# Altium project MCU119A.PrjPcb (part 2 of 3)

## Sheet MCU119A_USB_and_Power.SchDoc
size 431 x 279 mm; Date: Not shown in title block; ApprovedBy: Not shown in title block; CheckedBy: Not shown in title block; Author: Not shown in title block; CompanyName: Not shown in title block; Engineer: Not shown in title block; Organization: Not shown in title block; Address1: Not shown in title block; Address2: Not shown in title block; Address3: Not shown in title block; Address4: Not shown in title block; DocumentNumber: 7; Revision: Use project parameter SCH_Rev; SheetNumber: 5; SheetTotal: 8; PageSetup: Record=PageOptions¦CenterHorizontal=True¦CenterVertical=True¦PrintScale=1.00¦XCorrection=1.00¦YCorrection=1.00¦PrintKind=0¦BorderSize=5000000¦LeftOffset=0¦BottomOffset=0¦Orientation=2¦PaperLength=1000¦PaperWidth=1000¦Scale=100¦PaperSource=15¦PrintQuality=600¦MediaType=1¦DitherType=10¦PaperKind=Letter¦PrintScaleMode=1
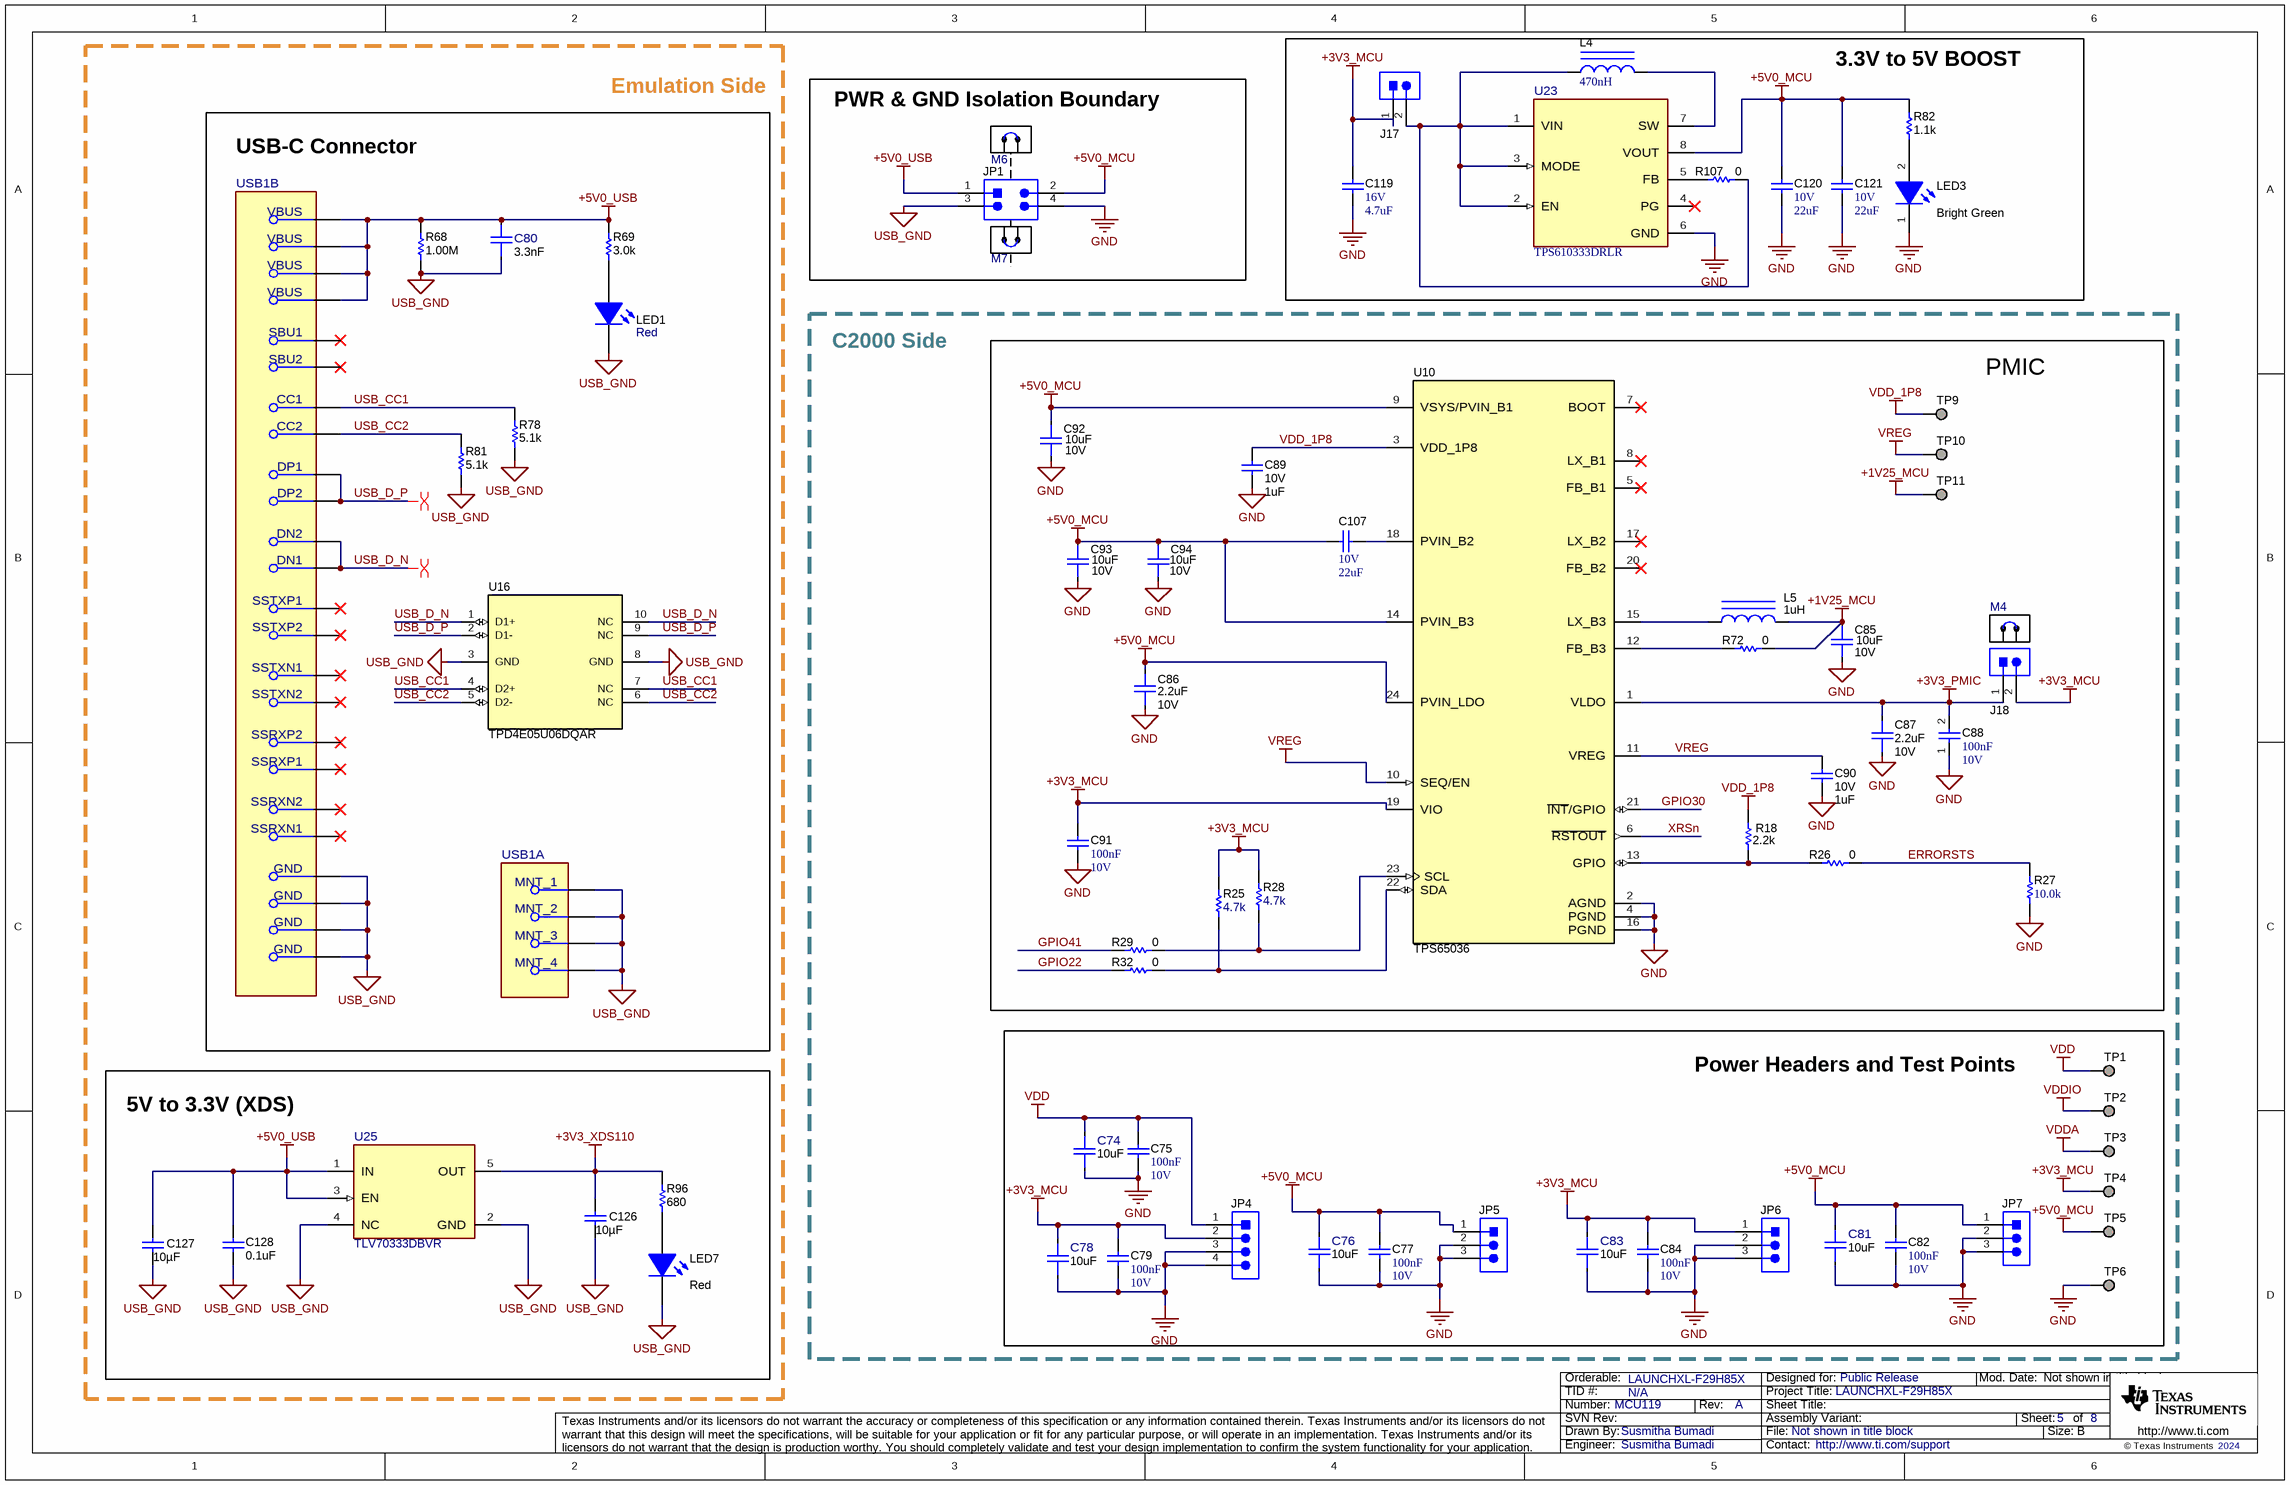
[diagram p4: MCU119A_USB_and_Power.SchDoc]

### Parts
C74  ValueDisplayed: 10uF  [FP-CC0603KRX5R6BB106_0603-MFG]  (hidden comment: CC0603KRX5R6BB106)
C75  Cap_F: 100nF  VDC_V: 10V  [0603]  (hidden comment: C0603C104K8RACTU)
C76  ValueDisplayed: 10uF  [FP-CC0603KRX5R6BB106_0603-MFG]  (hidden comment: CC0603KRX5R6BB106)
C77  Cap_F: 100nF  VDC_V: 10V  [0603]  (hidden comment: C0603C104K8RACTU)
C78  ValueDisplayed: 10uF  [FP-CC0603KRX5R6BB106_0603-MFG]  (hidden comment: CC0603KRX5R6BB106)
C79  Cap_F: 100nF  VDC_V: 10V  [0603]  (hidden comment: C0603C104K8RACTU)
C80  ValueDisplayed: 3.3nF  [FP-885012205064_0402-MFG]  (hidden comment: 885012205064)
C81  ValueDisplayed: 10uF  [FP-CC0603KRX5R6BB106_0603-MFG]  (hidden comment: CC0603KRX5R6BB106)
C82  Cap_F: 100nF  VDC_V: 10V  [0603]  (hidden comment: C0603C104K8RACTU)
C83  ValueDisplayed: 10uF  [FP-CC0603KRX5R6BB106_0603-MFG]  (hidden comment: CC0603KRX5R6BB106)
C84  Cap_F: 100nF  VDC_V: 10V  [0603]  (hidden comment: C0603C104K8RACTU)
C85  VDC_V: 10V  ValueDisplayed: 10uF  [FP-CGA4J3X7S1A106K125AE_0805-MFG]  (hidden comment: CGA4J3X7S1A106K125AE)
C86  ValueDisplayed: 2.2uF  VDC_V: 10V  [FP-CGA3E3X7S1A225K080AB_0603-MFG]  (hidden comment: CGA3E3X7S1A225K080AB)
C87  ValueDisplayed: 2.2uF  VDC_V: 10V  [FP-CGA3E3X7S1A225K080AB_0603-MFG]  (hidden comment: CGA3E3X7S1A225K080AB)
C88  Cap_F: 100nF  VDC_V: 10V  [0603]  (hidden comment: C0603C104K8RACTU)
C89  VDC_V: 10V  ValueDisplayed: 1uF  [0402_070]  (hidden comment: GCM155C71A105KE38D)
C90  VDC_V: 10V  ValueDisplayed: 1uF  [0402_070]  (hidden comment: GCM155C71A105KE38D)
C91  Cap_F: 100nF  VDC_V: 10V  [0603]  (hidden comment: C0603C104K8RACTU)
C92  VDC_V: 10V  ValueDisplayed: 10uF  [FP-CGA4J3X7S1A106K125AE_0805-MFG]  (hidden comment: CGA4J3X7S1A106K125AE)
C93  VDC_V: 10V  ValueDisplayed: 10uF  [FP-CGA4J3X7S1A106K125AE_0805-MFG]  (hidden comment: CGA4J3X7S1A106K125AE)
C94  VDC_V: 10V  ValueDisplayed: 10uF  [FP-CGA4J3X7S1A106K125AE_0805-MFG]  (hidden comment: CGA4J3X7S1A106K125AE)
C107  VDC_V: 10V  ValueDisplayed: 22uF  [0603]  (hidden comment: GRM188R61A226ME15D)
C119  VDC_V: 16V  ValueDisplayed: 4.7uF  [0603]  (hidden comment: GRM188R61C475KAAJ)
C120  VDC_V: 10V  ValueDisplayed: 22uF  [0603]  (hidden comment: GRM188R61A226ME15D)
C121  VDC_V: 10V  ValueDisplayed: 22uF  [0603]  (hidden comment: GRM188R61A226ME15D)
C126  ValueDisplayed: 10µF  [0402_080]  (hidden comment: 0402ZD106MAT2A)
C127  ValueDisplayed: 10µF  [0402_080]  (hidden comment: 0402ZD106MAT2A)
C128  ValueDisplayed: 0.1uF  [0402]  (hidden comment: 885012205037)
J17  61300211121  [WURTH_61300211121]  (value not drawn)
J18  61300211121  [WURTH_61300211121]  (value not drawn)
JP1  TSM-102-01-L-DV  [Samtec_TSM-102-01-x-DV]  (value not drawn)
JP4  61300411121  [WURTH_61300411121]  (value not drawn)
JP5  61300311121  [WURTH_61300311121]  (value not drawn)
JP6  61300311121  [WURTH_61300311121]  (value not drawn)
JP7  61300311121  [WURTH_61300311121]  (value not drawn)
L4  ValueDisplayed: 470nH  [IHHP-1008AB]  (hidden comment: IHHP1008ABERR47M01)
L5  ValueDisplayed: 1uH  [TFM252012]  (hidden comment: TFM252012ALMA1R0MTAA)
LED1  value Red  [WL-SMCW_RED_0805]  (hidden comment: 150080SS75000)
LED3  value Bright Green  [WL-SMCW_Green_0805]  (hidden comment: 150080VS75000)
LED7  value Red  [WL-SMCW_RED_0805]  (hidden comment: 150080SS75000)
M4  60900213421  [Wurth_60900213421]  (value not drawn)
M6  60900213421  [Wurth_60900213421]  (value not drawn)
M7  60900213421  [Wurth_60900213421]  (value not drawn)
R18  ValueDisplayed: 2.2k  [0402]  (hidden comment: CRCW04022K20JNED)
R25  ValueDisplayed: 4.7k  [0402]  (hidden comment: CRCW04024K70JNED)
R26  ValueDisplayed: 0  [0402]  (hidden comment: RC0402JR-070RL)
R27  ValueDisplayed: 10.0k  [0402]  (hidden comment: AC0402FR-0710KL)
R28  ValueDisplayed: 4.7k  [0402]  (hidden comment: CRCW04024K70JNED)
R29  ValueDisplayed: 0  [0402]  (hidden comment: RC0402JR-070RL)
R32  ValueDisplayed: 0  [0402]  (hidden comment: RC0402JR-070RL)
R68  ValueDisplayed: 1.00M  [0402]  (hidden comment: CRCW04021M00FKED)
R69  ValueDisplayed: 3.0k  [0603]  (hidden comment: RC0603JR-073KL)
R72  ValueDisplayed: 0  [0402]  (hidden comment: RC0402JR-070RL)
R78  ValueDisplayed: 5.1k  [0603]  (hidden comment: RC0603JR-075K1L)
R81  ValueDisplayed: 5.1k  [0603]  (hidden comment: RC0603JR-075K1L)
R82  ValueDisplayed: 1.1k  [0402]  (hidden comment: CRCW04021K10JNED)
R96  ValueDisplayed: 680  [0402]  (hidden comment: CRCW0402680RJNED)
R107  ValueDisplayed: 0  [0402]  (hidden comment: RC0402JR-070RL)
TP1  TESTPOINT  [TP_50MIL-25MILHOLE]  (value not drawn)  (no BOM)
TP2  TESTPOINT  [TP_50MIL-25MILHOLE]  (value not drawn)  (no BOM)
TP3  TESTPOINT  [TP_50MIL-25MILHOLE]  (value not drawn)  (no BOM)
TP4  TESTPOINT  [TP_50MIL-25MILHOLE]  (value not drawn)  (no BOM)
TP5  TESTPOINT  [TP_50MIL-25MILHOLE]  (value not drawn)  (no BOM)
TP6  TESTPOINT  [TP_50MIL-25MILHOLE]  (value not drawn)  (no BOM)
TP9  TESTPOINT  [TP_50MIL-25MILHOLE]  (value not drawn)  (no BOM)
TP10  TESTPOINT  [TP_50MIL-25MILHOLE]  (value not drawn)  (no BOM)
TP11  TESTPOINT  [TP_50MIL-25MILHOLE]  (value not drawn)  (no BOM)
U10  TPS65036  [RAY0024B-MFG]
U16  TPD4E05U06DQAR  [DQA0010A]
U23  TPS610333DRLR  [DRL0008A-MFG]
U25  TLV70333DBVR  [DBV0005A-MFG]
USB1  MUP-U22001  [FP-MUP-U22001_CONN_USB_8MM94_8MM0-MFG]  (value not drawn)  (parts A,B of 2)

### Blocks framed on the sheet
3.3V to 5V BOOST: C119-C121 J17 L4 LED3 R82 R107 U23
USB-C Connector: C80 LED1 R68 R69 R78 R81 U16 USB1
PWR & GND Isolation Boundary: JP1 M6 M7
PMIC: C85-C94 C107 J18 L5 M4 R18 R25-R29 R32 R72 TP9-TP11 U10
5V to 3.3V (XDS): C126-C128 LED7 R96 U25
Power Headers and Test Points: C74-C79 C81-C84 JP4-JP7 TP1-TP6

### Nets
+1V25_MCU: C85.1 L5.2 R72.2 TP11.1
+3V3_MCU: C78.2 C79.1 C83.2 C84.1 C91.1 C119.1 J17.1 J18.2 JP4.2 JP6.1 R25.2 R28.2 TP4.1 U10.19(VIO)
+3V3_PMIC: C87.2 C88.2 J18.1 U10.1(VLDO)
+3V3_XDS110: C126.1 R96.1 U25.5(OUT)
+5V0_MCU: C76.2 C77.1 C81.2 C82.1 C86.2 C92.1 C93.1 C94.1 C107.2 C120.1 C121.1 JP1.2 JP5.1 JP7.1 R82.2 TP5.1 U10.9(VSYS/PVIN_B1) U10.14(PVIN_B3) U10.24(PVIN_LDO) U23.8(VOUT)
+5V0_USB: C80.2 C127.1 C128.1 JP1.1 R68.2 R69.2 U25.1(IN) U25.3(EN) USB1.A4(VBUS) USB1.A9(VBUS) USB1.B4(VBUS) USB1.B9(VBUS)
GND: C74.1 C75.1 C76.1 C77.2 C78.1 C79.2 C81.1 C82.2 C83.1 C84.2 C85.2 C86.1 C87.1 C88.1 C89.2 C90.2 C91.2 C92.2 C93.2 C94.2 C119.2 C120.2 C121.2 JP1.4 JP4.3 JP4.4 JP5.2 JP5.3 JP6.2 JP6.3 JP7.2 JP7.3 LED3.1(K) R27.1 TP6.1 U10.2(AGND) U10.4(PGND) U10.16(PGND) U23.6(GND)
USB_GND: C80.1 C126.2 C127.2 C128.2 JP1.3 LED1.1(K) LED7.1(K) R68.1 R78.1 R81.1 U16.3(GND) U16.8(GND) U25.2(GND) U25.4(NC) USB1.1(MNT_1) USB1.2(MNT_2) USB1.3(MNT_3) USB1.4(MNT_4) USB1.A1(GND) USB1.A12(GND) USB1.B1(GND) USB1.B12(GND)
VDD: C74.2 C75.2 JP4.1 TP1.1
VDD_1P8: C89.1 R18.2 TP9.1 U10.3(VDD_1P8)
VDDA: TP3.1
VDDIO: TP2.1
VREG: C90.1 TP10.1 U10.10(SEQ/EN) U10.11(VREG)
ERRORSTS: R26.2 R27.2
GPIO22: R32.1
GPIO30: U10.21(~{INT}/GPIO)
GPIO41: R29.1
USB_CC1: R78.2 U16.4(D2+) U16.7(NC) USB1.A5(CC1)
USB_CC2: R81.2 U16.5(D2-) U16.6(NC) USB1.B5(CC2)
USB_D_N: U16.1(D1+) U16.10(NC) USB1.A7(DN1) USB1.B7(DN2)
USB_D_P: U16.2(D1-) U16.9(NC) USB1.A6(DP1) USB1.B6(DP2)
XRSn: U10.6(~{RSTOUT})
NetC107_1: C107.1 U10.18(PVIN_B2)
NetJ17_2: J17.2 L4.1 R107.2 U23.1(VIN) U23.2(EN) U23.3(MODE)
NetL4_2: L4.2 U23.7(SW)
NetL5_1: L5.1 U10.15(LX_B3)
NetLED1_2: LED1.2(A) R69.1
NetLED3_2: LED3.2(A) R82.1
NetLED7_2: LED7.2(A) R96.2
NetR18_1: R18.1 R26.1 U10.13(GPIO)
NetR25_1: R25.1 R32.2 U10.22(SDA)
NetR28_1: R28.1 R29.2 U10.23(SCL)
NetR72_1: R72.1 U10.12(FB_B3)
NetR107_1: R107.1 U23.5(FB)

Not connected (* = marked no-connect by the designer): U10 5(FB_B1)* 7(BOOT)* 8(LX_B1)* 17(LX_B2)* 20(FB_B2)*; U23 4(PG)*; USB1 A2(SSTXP1)* A3(SSTXN1)* A8(SBU1)* A10(SSRXN2)* A11(SSRXP2)* B2(SSTXP2)* B3(SSTXN2)* B8(SBU2)* B10(SSRXN1)* B11(SSRXP1)*

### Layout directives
differential pair: USB_D_N, USB_D_P

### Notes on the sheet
- Emulation Side
- C2000 Side

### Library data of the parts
C74 C76 C78 C81 C83 = CMP-0092309-1: Cap Ceramic 10uF 10V X5R 10% SMD 0603 85C Paper T/R; Manufacturer: YAGEO; Cap_F: 10µF; TempCo: 15%; Category 7542B8484461Ae85: Passive Components; Category 4C11811B7D3097D6: Single Components; SizeZ_mm: 1mm; Category F8883582C9A8234F: Capacitors; AEC Qualified: No; Value: 10µF; Category 85Ce48C4B2B95E09: Uncategorized
C75 C77 C79 C82 C84 C88 C91 = CMP-0006862-5: CAP, CERM, 0.1 uF, 10 V, +/- 10%, X7R, 0603; Manufacturer: Kemet; TaMin_C: -55°C; Polarized: N; SizeAreaWB_mm2: 4.68; Value1: Unknown; U/M: EA; Value: 0.1uF; TaMax_C: 125°C; SizeZ_mm: 1; SizeX_mm: 1.6; SizeY_mm: 0.8; SizeArea_mm2: 1.28; AEC Category: Q200
C80 = CMP-0092424-1: Cap Cer 3300pF 50V X7R 0402; Manufacturer: Wurth Electronics; TempCo: 15%; AEC Qualified: No; Value: 3.3nF; SizeZ_mm: 0.55mm; Tolerance_%: 10%
C85 C92-C94 = CMP-0089543-1: 10µF ±10% 10V Ceramic Capacitor X7S 0805 (2012 Metric); Manufacturer: TDK; SizeZ_mm: 1.5mm; AEC Grade: Grade 1; AEC Qualified: Yes; TempCo: 22%
C86 C87 = CMP-0094207-1: Cap Ceramic 2.2uF 10V X7S 10% Pad SMD 0603 +125°C Automotive T/R; Manufacturer: TDK; Tolerance_%: 0.1%; AEC Grade: Grade 1; TempCo: 0.22; Cap_F: 2.2µF; SizeZ_mm: 1.1mm; AEC Qualified: Yes; Value: 2.2µF
C89 C90 = CMP-0006349-2: CAP, CERM, 1 uF, 10 V, +/- 10%, X7S, AEC-Q200 Grade 1, 0402; Manufacturer: MuRata; TaMin_C: -55°C; Polarized: N; SizeAreaWB_mm2: 3; Value1: Unknown; U/M: EA; Value: 1uF; TaMax_C: 125°C; SizeZ_mm: 0.7; SizeX_mm: 1; SizeY_mm: 0.5; Cap_Case: 0402; AEC Qualified: Y; Cap_F: 1µF; AEC Category: Q200
C107 C120 C121 = CMP-0007324-5: CAP, CERM, 22 uF, 10 V, +/- 20%, X5R, 0603; Manufacturer: MuRata; TaMin_C: -55°C; Polarized: N; SizeAreaWB_mm2: 4.68; Value1: Unknown; U/M: EA; Value: 22uF; TaMax_C: 85°C; SizeZ_mm: 1; SizeX_mm: 1.6; SizeY_mm: 0.8; SizeArea_mm2: 1.28; Cap_F: 22µF; AEC Category: Q200
C119 = CMP-0007341-5: CAP, CERM, 4.7 uF, 16 V, +/- 10%, X5R, 0603; Manufacturer: MuRata; TaMin_C: -55°C; Polarized: N; SizeAreaWB_mm2: 4.68; Value1: Unknown; U/M: EA; Value: 4.7uF; TaMax_C: 85°C; SizeZ_mm: 1; SizeX_mm: 1.6; SizeY_mm: 0.8; SizeArea_mm2: 1.28; Cap_F: 4.7µF; AEC Category: Q200
C126 C127 = CMP-0078623-1: CAP, CERM, 10 µF, 10 V,+/- 20%, X5R, 0402; Manufacturer: AVX; SizeAreaWB_mm2: 3; SizeArea_mm2: 0.5; AEC Qualified: N; AEC Category: Q200; Value: 10uF; TaMax_C: 85°C; SizeZ_mm: 0.8; TaMin_C: -55°C; VDC_V: 10V; U/M: EA; SizeX_mm: 1
C128 = CMP-0006228-2: CAP, CERM, 0.1 uF, 16 V, +/- 10%, X7R, 0402; Manufacturer: Wurth Elektronik; TaMin_C: -55°C; Polarized: N; SizeAreaWB_mm2: 3; Value1: Unknown; U/M: EA; Value: 0.1uF; TaMax_C: 125°C; SizeZ_mm: 0.6; SizeX_mm: 1; SizeY_mm: 0.5; Value2: 16V; Cap_F: 100nF; AEC Category: Q200
J17 J18 = CMP-0054794-2: Header, 2.54 mm, 2x1, Gold, TH; Manufacturer: Wurth Elektronik; Shrouded: N; Gender: Male; Green_REACh: Passed; Pitch_mm: 2.54; Green_Lifecycle: Active; Row_Count: 1; Cert_UL: Y
JP1 = CMP-0055559-1: Header, 2.54mm, 2x2, Gold, SMT; Manufacturer: Samtec; CNHeader: TRUE; Shrouded: N; Gender: Male; Cert_CSA: Y; Voltage_V: 475V; Row_Count: 2; Pitch_mm: 2.54; CT: FALSE
JP4 = CMP-0054798-2: Header, 2.54 mm, 4x1, Gold, TH; Manufacturer: Wurth Elektronik; Pitch_mm: 2.54; Gender: Male; Row_Count: 1; Cert_UL: Y; Shrouded: N
JP5-JP7 = CMP-0054796-4: Header, 2.54 mm, 3x1, Gold, TH; Manufacturer: Wurth Elektronik; Green_Lifecycle: Active; Green_REACh: Passed; CNHeader: TRUE; CT: FALSE
L4 = CMP-0063237-1: Inductor, Shielded, 470 nH, 4 A, 0.026 ohm, SMD; Manufacturer: Vishay-Dale; Isat: 4.55A @ 30% inductance drop; Irms: 4A @ 40C rise; SizeAreaWB_mm2: 10.5; DCR_ohm: 26m; Value: 470nH; Imax_A: 4A; SizeZ_mm: 1.2; SizeX_mm: 2.5; SizeY_mm: 2; SizeArea_mm2: 5; AEC Qualified: N; AEC Category: Q200
L5 = CMP-0062879-1: Inductor, Film, 1 uH, 3.7 A, 0.042 ohm, AEC-Q200 Grade 0, SMD; Manufacturer: TDK; Isat: 4.1A @ 30% inductance drop; Irms: 3.7A @ 40C rise; Green_Lifecycle: Not Set; SizeAreaWB_mm2: 10.5; DCR_ohm: 42m; Green_REACh: Incomplete; Value: 1uH; Imax_A: 3.7A; SizeZ_mm: 1.2; SizeX_mm: 2.5; SizeY_mm: 2; SizeArea_mm2: 5; Ind_H: 1µH; AEC Qualified: Y; AEC Grade: 0; AEC Category: Q200
LED1 LED7 = CMP-0002951-3: LED, Red, SMD; Manufacturer: Wurth Elektronik; Type: AlInGaP; Vf_V: 1.9V; Io_A: 30mA; Vr_V: 5V; Ir_A: 25µA; Tjmax_C: 85°C; Power_TotalModule: 72mW; Value1: 0.072W; Angle: 140
LED3 = CMP-0002960-2: LED, Bright Green, SMD; Manufacturer: Wurth Elektronik; Type: AlInGaP; Vf_V: 2V; Io_A: 20mA; Vr_V: 5V; Tjmax_C: 85°C; Power_TotalModule: 72mW; Value1: 0.072W; Angle: 140; U/M: EA
M4 M6 M7 = CMP-0003761-2: Shunt, 2.54mm, Gold, Black; Manufacturer: Wurth Elektronik
R18 = CMP-0026890-5: RES, 2.2 k, 5%, 0.063 W, AEC-Q200 Grade 0, 0402; Manufacturer: Vishay-Dale; Value: 2.2k; Value_Code: 2k20; Power_W: 63mW; Value2: 0.063W; VDC_V: 50V; TempCo: 200 ppm/C; SizeArea_mm2: 0.5; SizeX_mm: 1; SizeZ_mm: 0.6; EIA_Code: E24; AEC Category: Q200; AEC Qualified: Y; AEC Grade: 0
R25 R28 = CMP-0026938-1: RES, 4.7 k, 5%, 0.063 W, 0402; Manufacturer: Vishay-Dale; Power_W: 63mW; TempCo: 200 ppm/C; Value_Code: 4k70; U/M: EA; Value: 4.7k; EIA_Code: E24; SizeX_mm: 1; SizeY_mm: 0.5; SizeZ_mm: 0.6; Value2: 0.063W; VDC_V: 50V; AEC Category: Q200
R26 R29 R32 R72 R107 = CMP-0027004-2: RES, 0, 5%, 0.063 W, 0402; Manufacturer: Yageo America; Power_W: 63mW; TempCo: 200 ppm/C; Value_Code: 0000; U/M: EA; Value: 0; EIA_Code: E24; SizeX_mm: 1; SizeY_mm: 0.5; SizeZ_mm: 0.6; Value2: 0.063W; VDC_V: 50V; AEC Category: Q200
R27 = CMP-0077731-1: RES, 10.0 k, 1%, 0.063 W, AEC-Q200 Grade 0, 0402; Manufacturer: Yageo America; Power_W: 63mW; TempCo: 100 ppm/C; Value_Code: 10k0; U/M: EA; Value: 10.0k; EIA_Code: E96; Res_ohm: 10k; SizeX_mm: 1.0; SizeY_mm: 0.5; SizeZ_mm: 0.6; Value2: 0.063W; AEC Qualified: Y; VDC_V: 50V; AEC Grade: 0; AEC Category: Q200
R68 = CMP-0026100-2: RES, 1.00 M, 1%, 0.063 W, AEC-Q200 Grade 0, 0402; Manufacturer: Vishay-Dale; Value: 1.00Meg; Res_ohm: 1M; Value_Code: 1M00; Power_W: 63mW; Value2: 0.063W; VDC_V: 50V; TempCo: 100 ppm/C; SizeArea_mm2: 0.5; SizeX_mm: 1; SizeZ_mm: 0.6; EIA_Code: E96; AEC Category: Q200; AEC Qualified: Y; AEC Grade: 0
R69 = CMP-0025921-5: RES, 3.0 k, 5%, 0.1 W, 0603; Manufacturer: Yageo; Power_W: 100mW; TempCo: 100 ppm/C; Value_Code: 3k00; Value: 3.0k; EIA_Code: E24; Res_ohm: 3k; SizeX_mm: 1.6; SizeY_mm: 0.8; SizeZ_mm: 1; Value2: 0.1W; SizeArea_mm2: 1.28; AEC Qualified: N; VDC_V: 75V; AEC Category: Q200; SizeAreaWB_mm2: 4.68
R78 R81 = CMP-0025932-5: RES, 5.1 k, 5%, 0.1 W, 0603; Manufacturer: Yageo; Power_W: 100mW; TempCo: 100 ppm/C; Value_Code: 5k10; Value: 5.1k; EIA_Code: E24; SizeX_mm: 1.6; SizeY_mm: 0.8; SizeZ_mm: 1; Value2: 0.1W; SizeArea_mm2: 1.28; AEC Qualified: N; VDC_V: 75V; AEC Category: Q200; SizeAreaWB_mm2: 4.68
R82 = CMP-0026853-5: RES, 1.1 k, 5%, 0.063 W, AEC-Q200 Grade 0, 0402; Manufacturer: Vishay-Dale; Power_W: 63mW; TempCo: 200 ppm/C; Value_Code: 1k10; Value: 1.1k; EIA_Code: E24; SizeX_mm: 1; SizeY_mm: 0.5; SizeZ_mm: 0.6; Value2: 0.063W; AEC Qualified: Y; VDC_V: 50V; AEC Category: Q200; AEC Grade: 0
R96 = CMP-0026962-3: RES, 680, 5%, 0.063 W, AEC-Q200 Grade 0, 0402; Manufacturer: Vishay-Dale; Value: 680; Value_Code: 680R; Power_W: 63mW; Value2: 0.063W; VDC_V: 50V; TempCo: 200 ppm/C; EIA_Code: E24; AEC Category: Q200; AEC Qualified: Y; AEC Grade: 0; SizeArea_mm2: 0.5; SizeX_mm: 1; SizeZ_mm: 0.6
TP1-TP6 TP9-TP11 = CMP-0078143-4: TEST POINT.  No entry in BOM.
U10 = CMP-0119993-1: Automotive Camera PMIC; Manufacturer: Texas Instruments; SizeZ_mm: 1mm; AEC Qualified: Yes; AEC Grade: Grade 1; Max Supply Voltage: 35V; Min Supply Voltage: 4V; Number Of Outputs: 4; Output Voltage: 3-5.5/0.6-3.4/0.6-3.4/1.8-3.4V; Standoff Height: 0mm; TaMax_C: +125°C; TaMin_C: -40°C; TJmax_C: +150°C
U16 = CMP-0073613-3: 4-Channel Ultra-Low-Capacitance IEC ESD Protection Diode, DQA0010A (USON-10); Alternate Manufacturer: Texas Instruments; Green_Lifecycle: Active; SizeAreaWB_mm2: 7.0; Green_REACh: Passed; SizeZ_mm: 0.55; SizeX_mm: 1.0; SizeY_mm: 2.5; CompType: IC; AEC Category: Q200; AEC Qualified: N
U23 = CMP-0122273-1: 5-V, 1.85-A boost converter with power good, output discharge and PFM/PWM control 8-SOT-5X3 -40 to 125; Manufacturer: Texas Instruments; SizeZ_mm: 0.6mm; AEC Qualified: No; Max Supply Voltage: 5.5V; Min Supply Voltage: 1.8V; Nominal Supply Current: 20uA; Number Of Outputs: 1; Output Type: Fixed; Output Voltage: 5V; Standoff Height: 0mm; Switching Frequency: 2.4MHz; TJmax_C: +125°C
U25 = CMP-0091939-1: Linear Voltage Regulator IC Positive Fixed 1 Output 300mA SOT-23-5; Manufacturer: Texas Instruments; SizeZ_mm: 1.45mm; Nominal Supply Current: 35-370uA; TJmax_C: +125°C; Output Voltage: 3.3V; Dropout Voltage: 260mV; Standoff Height: 0mm; Accuracy Percentage: 2%; AEC Qualified: No; Max Supply Voltage: 5.5V; Number Of Outputs: 1; Min Supply Voltage: 2V
USB1 = CMP-0092137-1: Connector, USB Type-C 24 pin Mid Mount dual row Receptacle Surface Mount; Manufacturer: MUP; ContactFinish: Gold,Nickel; Usb Standard: OTHER; AEC Qualified: No; Conn Orientation: Horizontal; Shrouded: true; SizeZ_mm: 2.81mm; Is Female: yes; DUT-Pitch_mm: 0.5mm

## Sheet MCU119A_XDS110_MCU.SchDoc
size 431 x 279 mm; Date: Not shown in title block; ApprovedBy: Not shown in title block; CheckedBy: Not shown in title block; Author: Not shown in title block; CompanyName: Not shown in title block; Engineer: Not shown in title block; Organization: Not shown in title block; Address1: Not shown in title block; Address2: Not shown in title block; Address3: Not shown in title block; Address4: Not shown in title block; DocumentNumber: 8; Revision: Use project parameter SCH_Rev; SheetNumber: 6; SheetTotal: 8; PageSetup: Record=PageOptions¦CenterHorizontal=True¦CenterVertical=True¦PrintScale=1.00¦XCorrection=1.00¦YCorrection=1.00¦PrintKind=0¦BorderSize=5000000¦LeftOffset=0¦BottomOffset=0¦Orientation=2¦PaperLength=1000¦PaperWidth=1000¦Scale=100¦PaperSource=15¦PrintQuality=600¦MediaType=1¦DitherType=10¦PaperKind=Letter¦PrintScaleMode=1
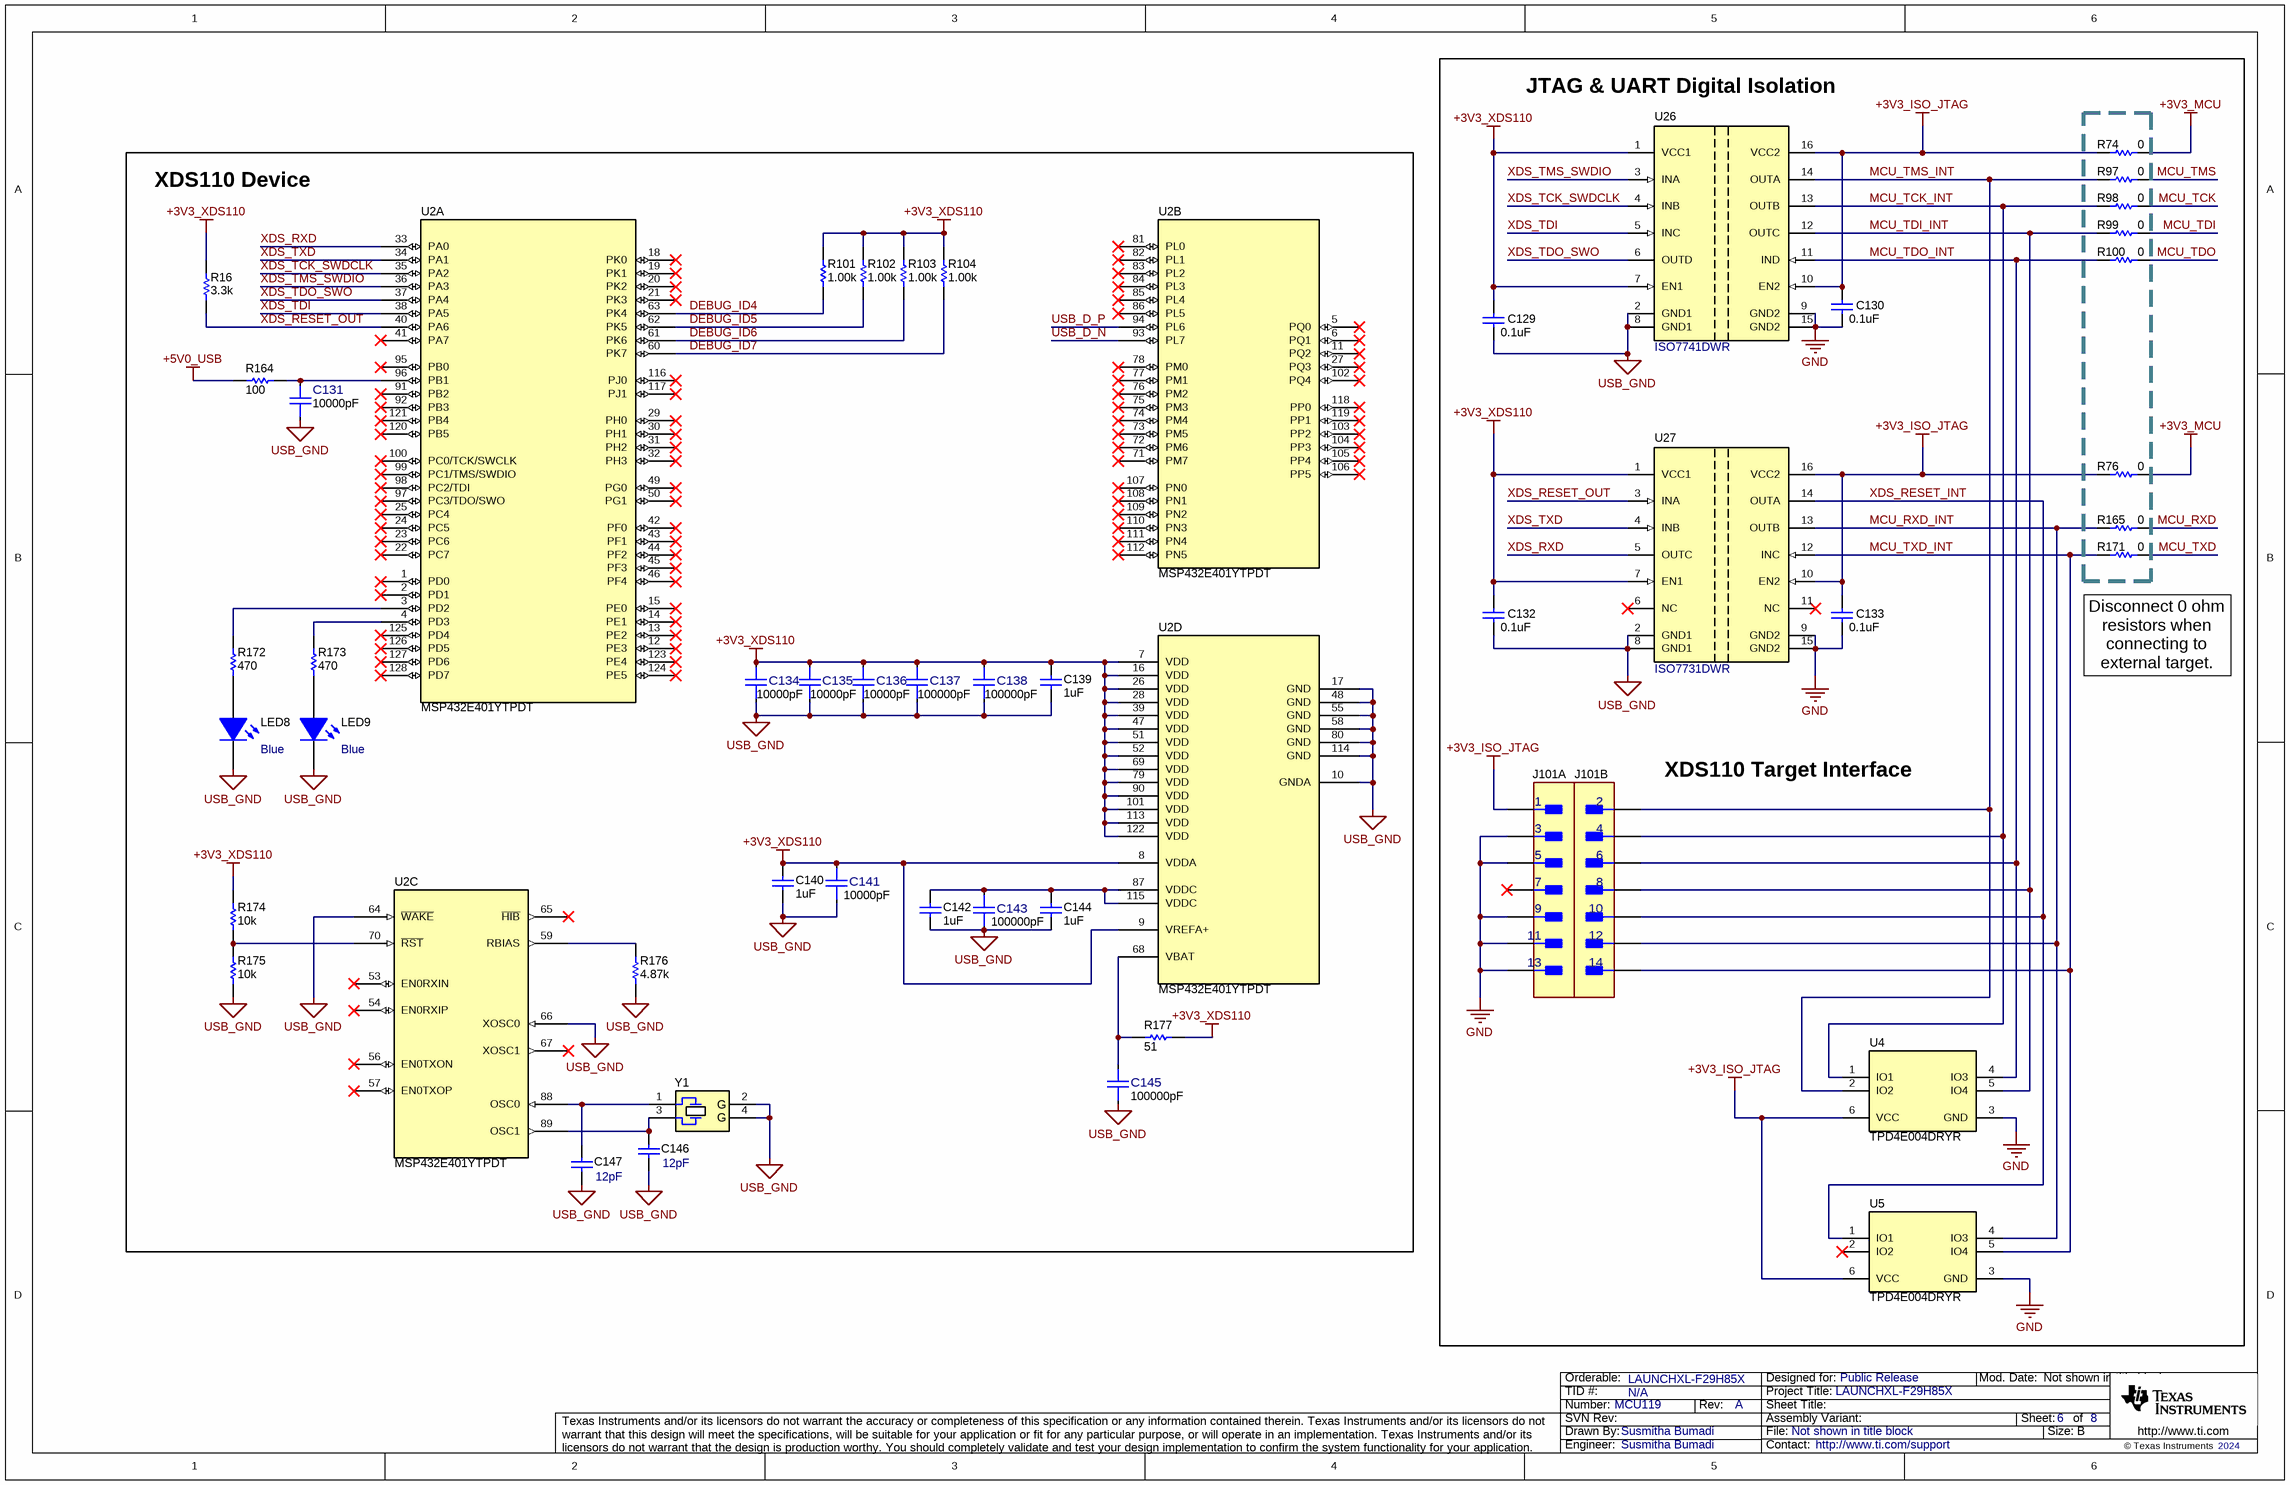
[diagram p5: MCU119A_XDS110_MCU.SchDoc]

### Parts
C129  ValueDisplayed: 0.1uF  [0402]  (hidden comment: 885012205037)
C130  ValueDisplayed: 0.1uF  [0402]  (hidden comment: 885012205037)
C131  ValueDisplayed: 10000pF  [FP-885012205050_0402-MFG]  (hidden comment: 885012205050)
C132  ValueDisplayed: 0.1uF  [0402]  (hidden comment: 885012205037)
C133  ValueDisplayed: 0.1uF  [0402]  (hidden comment: 885012205037)
C134  ValueDisplayed: 10000pF  [FP-885012205050_0402-MFG]  (hidden comment: 885012205050)
C135  ValueDisplayed: 10000pF  [FP-885012205050_0402-MFG]  (hidden comment: 885012205050)
C136  ValueDisplayed: 10000pF  [FP-885012205050_0402-MFG]  (hidden comment: 885012205050)
C137  ValueDisplayed: 100000pF  [FP-885012205018_0402-MFG]  (hidden comment: 885012205018)
C138  ValueDisplayed: 100000pF  [FP-885012205018_0402-MFG]  (hidden comment: 885012205018)
C139  ValueDisplayed: 1uF  [0402]  (hidden comment: 885012105012)
C140  ValueDisplayed: 1uF  [0402]  (hidden comment: 885012105012)
C141  ValueDisplayed: 10000pF  [FP-885012205050_0402-MFG]  (hidden comment: 885012205050)
C142  ValueDisplayed: 1uF  [0402]  (hidden comment: 885012105012)
C143  ValueDisplayed: 100000pF  [FP-885012205018_0402-MFG]  (hidden comment: 885012205018)
C144  ValueDisplayed: 1uF  [0402]  (hidden comment: 885012105012)
C145  ValueDisplayed: 100000pF  [FP-885012205018_0402-MFG]  (hidden comment: 885012205018)
C146  ValueDisplayed: 12pF  [0402]  (hidden comment: CL05C120JB5NNNC)
C147  ValueDisplayed: 12pF  [0402]  (hidden comment: CL05C120JB5NNNC)
J101  FTSH-107-01-F-DV-K  [FP-FTSH-107-01-F-DV-K_HDR14-MFG]  (value not drawn)  (parts A,B of 2)
LED8  value Blue  [LTST-C170TBKT_Blue]  (hidden comment: LTST-C170TBKT)
LED9  value Blue  [LTST-C170TBKT_Blue]  (hidden comment: LTST-C170TBKT)
R16  ValueDisplayed: 3.3k  [0402]  (hidden comment: CRCW04023K30JNED)
R74  ValueDisplayed: 0  [0603]  (hidden comment: ERJ-3GEY0R00V)
R76  ValueDisplayed: 0  [0603]  (hidden comment: ERJ-3GEY0R00V)
R97  ValueDisplayed: 0  [0603]  (hidden comment: ERJ-3GEY0R00V)
R98  ValueDisplayed: 0  [0603]  (hidden comment: ERJ-3GEY0R00V)
R99  ValueDisplayed: 0  [0603]  (hidden comment: ERJ-3GEY0R00V)
R100  ValueDisplayed: 0  [0603]  (hidden comment: ERJ-3GEY0R00V)
R101  ValueDisplayed: 1.00k  [0402]  (hidden comment: CRCW04021K00FKED)
R102  ValueDisplayed: 1.00k  [0402]  (hidden comment: CRCW04021K00FKED)
R103  ValueDisplayed: 1.00k  [0402]  (hidden comment: CRCW04021K00FKED)
R104  ValueDisplayed: 1.00k  [0402]  (hidden comment: CRCW04021K00FKED)
R164  ValueDisplayed: 100  [0402]  (hidden comment: CRCW0402100RJNED)
R165  ValueDisplayed: 0  [0603]  (hidden comment: ERJ-3GEY0R00V)
R171  ValueDisplayed: 0  [0603]  (hidden comment: ERJ-3GEY0R00V)
R172  ValueDisplayed: 470  [0402]  (hidden comment: RC0402FR-07470RL)
R173  ValueDisplayed: 470  [0402]  (hidden comment: RC0402FR-07470RL)
R174  ValueDisplayed: 10k  [0402]  (hidden comment: CRCW040210K0JNED)
R175  ValueDisplayed: 10k  [0402]  (hidden comment: CRCW040210K0JNED)
R176  ValueDisplayed: 4.87k  [0402]  (hidden comment: CRCW04024K87FKED)
R177  ValueDisplayed: 51  [0402]  (hidden comment: CRCW040251R0JNED)
U2  MSP432E401YTPDT  [PDT0128A]  (parts A,B,C,D of 4)
U4  TPD4E004DRYR  [DRY0006A]
U5  TPD4E004DRYR  [DRY0006A]
U26  ISO7741DWR  [DW0016B_HV]
U27  ISO7731DWR  [DW0016B_HV]
Y1  NX3225GA-16.000M-STD-CRG-1  [NDK_NX3225GA]  (value not drawn)

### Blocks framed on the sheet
XDS110 Device: C131 C134-C147 LED8 LED9 R16 R101-R104 R164 R172-R177 U2 Y1

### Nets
+3V3_ISO_JTAG: C130.1 C133.1 J101.1 R74.1 R76.1 U4.6(VCC) U5.6(VCC) U26.10(EN2) U26.16(VCC2) U27.10(EN2) U27.16(VCC2)
+3V3_MCU: R74.2 R76.2
+3V3_XDS110: C129.1 C132.1 C134.2 C135.2 C136.2 C137.2 C138.2 C139.1 C140.1 C141.2 R16.2 R101.2 R102.2 R103.2 R104.2 R174.2 R177.2 U2.7(VDD) U2.8(VDDA) U2.9(VREFA+) U2.16(VDD) U2.26(VDD) U2.28(VDD) U2.39(VDD) U2.47(VDD) U2.51(VDD) U2.52(VDD) U2.69(VDD) U2.79(VDD) U2.90(VDD) U2.101(VDD) U2.113(VDD) U2.122(VDD) U26.1(VCC1) U26.7(EN1) U27.1(VCC1) U27.7(EN1)
+5V0_USB: R164.1
GND: C130.2 C133.2 J101.3 J101.5 J101.9 J101.11 J101.13 U4.3(GND) U5.3(GND) U26.9(GND2) U26.15(GND2) U27.9(GND2) U27.15(GND2)
USB_GND: C129.2 C131.1 C132.2 C134.1 C135.1 C136.1 C137.1 C138.1 C139.2 C140.2 C141.1 C142.2 C143.1 C144.2 C145.1 C146.2 C147.2 LED8.2(K) LED9.2(K) R175.1 R176.1 U2.10(GNDA) U2.17(GND) U2.48(GND) U2.55(GND) U2.58(GND) U2.64(~{WAKE}) U2.66(XOSC0) U2.80(GND) U2.114(GND) U26.2(GND1) U26.8(GND1) U27.2(GND1) U27.8(GND1) Y1.2(GND) Y1.4(GND)
DEBUG_ID4: R101.1 U2.63(PK4)
DEBUG_ID5: R102.1 U2.62(PK5)
DEBUG_ID6: R103.1 U2.61(PK6)
DEBUG_ID7: R104.1 U2.60(PK7)
MCU_RXD: R165.1
MCU_RXD_INT: J101.12 R165.2 U5.4(IO3) U27.13(OUTB)
MCU_TCK: R98.1
MCU_TCK_INT: J101.4 R98.2 U4.1(IO1) U26.13(OUTB)
MCU_TDI: R99.1
MCU_TDI_INT: J101.8 R99.2 U4.5(IO4) U26.12(OUTC)
MCU_TDO: R100.1
MCU_TDO_INT: J101.6 R100.2 U4.4(IO3) U26.11(IND)
MCU_TMS: R97.1
MCU_TMS_INT: J101.2 R97.2 U4.2(IO2) U26.14(OUTA)
MCU_TXD: R171.1
MCU_TXD_INT: J101.14 R171.2 U5.5(IO4) U27.12(INC)
USB_D_N: U2.93(PL7)
USB_D_P: U2.94(PL6)
XDS_RESET_INT: J101.10 U5.1(IO1) U27.14(OUTA)
XDS_RESET_OUT: R16.1 U2.40(PA6) U27.3(INA)
XDS_RXD: U2.33(PA0) U27.5(OUTC)
XDS_TCK_SWDCLK: U2.35(PA2) U26.4(INB)
XDS_TDI: U2.38(PA5) U26.5(INC)
XDS_TDO_SWO: U2.37(PA4) U26.6(OUTD)
XDS_TMS_SWDIO: U2.36(PA3) U26.3(INA)
XDS_TXD: U2.34(PA1) U27.4(INB)
NetC131_2: C131.2 R164.2 U2.96(PB1)
NetC142_1: C142.1 C143.2 C144.1 U2.87(VDDC) U2.115(VDDC)
NetC145_2: C145.2 R177.1 U2.68(VBAT)
NetC146_1: C146.1 U2.89(OSC1) Y1.3
NetC147_1: C147.1 U2.88(OSC0) Y1.1
NetLED8_1: LED8.1(A) R172.1
NetLED9_1: LED9.1(A) R173.1
NetR172_2: R172.2 U2.3(PD2)
NetR173_2: R173.2 U2.4(PD3)
NetR174_1: R174.1 R175.2 U2.70(~{RST})
NetR176_2: R176.2 U2.59(RBIAS)

Not connected (* = marked no-connect by the designer): J101 7*; U2 1(PD0)* 2(PD1)* 5(PQ0)* 6(PQ1)* 11(PQ2)* 12(PE3)* 13(PE2)* 14(PE1)* 15(PE0)* 18(PK0)* 19(PK1)* 20(PK2)* 21(PK3)* 22(PC7)* 23(PC6)* 24(PC5)* 25(PC4)* 27(PQ3)* 29(PH0)* 30(PH1)* 31(PH2)* 32(PH3)* 41(PA7)* 42(PF0)* 43(PF1)* 44(PF2)* 45(PF3)* 46(PF4)* 49(PG0)* 50(PG1)* 53(EN0RXIN)* 54(EN0RXIP)* 56(EN0TXON)* 57(EN0TXOP)* 65(~{HIB})* 67(XOSC1)* 71(PM7)* 72(PM6)* 73(PM5)* 74(PM4)* 75(PM3)* 76(PM2)* 77(PM1)* 78(PM0)* 81(PL0)* 82(PL1)* 83(PL2)* 84(PL3)* 85(PL4)* 86(PL5)* 91(PB2)* 92(PB3)* 95(PB0)* 97(PC3/TDO/SWO)* 98(PC2/TDI)* 99(PC1/TMS/SWDIO)* 100(PC0/TCK/SWCLK)* 102(PQ4)* 103(PP2)* 104(PP3)* 105(PP4)* 106(PP5)* 107(PN0)* 108(PN1)* 109(PN2)* 110(PN3)* 111(PN4)* 112(PN5)* 116(PJ0)* 117(PJ1)* 118(PP0)* 119(PP1)* 120(PB5)* 121(PB4)* 123(PE4)* 124(PE5)* 125(PD4)* 126(PD5)* 127(PD6)* 128(PD7)*; U5 2(IO2)*; U27 6(NC)* 11(NC)*

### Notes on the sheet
- JTAG & UART Digital Isolation
- (near R171) Disconnect 0 ohm resistors when connecting to external target.
- XDS110 Target Interface

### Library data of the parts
C129 C130 C132 C133 = CMP-0006228-2: as C128 on sheet MCU119A_USB_and_Power
C131 C134-C136 C141 = CMP-0090363-1: 10000pF ±10% 25V Ceramic Capacitor X7R 0402 (1005 Metric); Manufacturer: Wurth Electronics; SizeZ_mm: 0.55mm; Cap_F: 10nF; AEC Qualified: No; Value: 10nF; TempCo: 15%
C137 C138 C143 C145 = CMP-0090362-1: 0.1µF ±10% 10V Ceramic Capacitor X7R 0402 (1005 Metric); Manufacturer: Wurth Electronics; AEC Qualified: No; Value: 100nF; SizeZ_mm: 0.55mm; TempCo: 15%
C139 C140 C142 C144 = CMP-0064924-2: CAP, CERM, 1 uF, 10 V,+/- 20%, X5R, 0402; Manufacturer: Wurth Elektronik; Polarized: N; Value: 1uF; U/M: EA; Cap_F: 1µF; Value1: Unknown; VDC_V: 10V; TaMin_C: -55°C; TaMax_C: 85°C; SizeArea_mm2: 0.5; SizeAreaWB_mm2: 3; SizeX_mm: 1; SizeZ_mm: 0.6; AEC Category: Q200
C146 C147 = CMP-0006345-2: CAP, CERM, 12 pF, 50 V, +/- 5%, C0G/NP0, 0402; Manufacturer: Samsung Electro-Mechanics; TaMin_C: -55°C; Polarized: N; SizeAreaWB_mm2: 3; Value1: Unknown; U/M: EA; Value: 12pF; TaMax_C: 125°C; SizeZ_mm: 0.6; SizeX_mm: 1; SizeY_mm: 0.5; Value2: 50V; AEC Category: Q200
J101 = CMP-0092335-1: Connector, Header, Dual Row, 14 pin, .05" pitch/row spacing, Male, Shrouded, Keyed, IDC, SMT; Manufacturer: Samtec; Category 0836C53C3D42D3F1: Connectors; Category 75Fab8F04590Ae3D: Connectors and Adapters; ContactFinish: Gold,Nickel; Standoff Height: 0.15mm; Conn Orientation: Vertical; AEC Qualified: No; Category E7012A0Bd22E3Cc6: Headers & Receptacles; SizeZ_mm: 6.38mm; Category A3C16Ecb93907806: Uncategorized; DUT-Pitch_mm: 1.27mm; Current_A: 3.4A; Row_Count: 2
LED8 LED9 = CMP-0002889-2: LED, Blue, SMD; Manufacturer: Lite-On; Type: AlInGaP; Vf_V: 3.3V; Io_A: 20mA; Value1: W
R16 = CMP-0026918-5: RES, 3.3 k, 5%, 0.063 W, AEC-Q200 Grade 0, 0402; Manufacturer: Vishay-Dale; Value: 3.3k; Value_Code: 3k30; Power_W: 63mW; Value2: 0.063W; VDC_V: 50V; TempCo: 200 ppm/C; SizeArea_mm2: 0.5; SizeX_mm: 1; SizeZ_mm: 0.6; EIA_Code: E24; AEC Category: Q200; AEC Qualified: Y; AEC Grade: 0
R74 R76 R97-R100 R165 R171 = CMP-0025874-4: RES, 0, 5%, 0.1 W, AEC-Q200 Grade 0, 0603; Manufacturer: Panasonic; Power_W: 100mW; TempCo: 600 ppm/C; Value_Code: 0000; Value: 0; EIA_Code: E24; SizeX_mm: 1.6; SizeY_mm: 0.8; SizeZ_mm: 1; Value2: 0.1W; SizeArea_mm2: 1.28; AEC Qualified: Y; VDC_V: 50V; AEC Category: Q200; SizeAreaWB_mm2: 4.68
R101-R104 = CMP-0026071-3: RES, 1.00 k, 1%, 0.063 W, AEC-Q200 Grade 0, 0402; Manufacturer: Vishay-Dale; Power_W: 63mW; TempCo: 100 ppm/C; Value_Code: 1k00; Value: 1.00k; EIA_Code: E96; Res_ohm: 1k; SizeX_mm: 1; SizeY_mm: 0.5; SizeZ_mm: 0.6; Value2: 0.063W; AEC Qualified: Y; VDC_V: 50V; AEC Category: Q200; AEC Grade: 0
R164 = CMP-0026824-3: RES, 100, 5%, 0.063 W, AEC-Q200 Grade 0, 0402; Manufacturer: Vishay-Dale; Value: 100; Value_Code: 100R; Power_W: 63mW; Value2: 0.063W; VDC_V: 50V; TempCo: 200 ppm/C; SizeArea_mm2: 0.5; SizeX_mm: 1; SizeZ_mm: 0.6; EIA_Code: E24; AEC Category: Q200; AEC Qualified: Y; AEC Grade: 0
R172 R173 = CMP-0026736-1: RES, 470, 1%, 0.063 W, 0402; Manufacturer: Yageo America; Power_W: 63mW; TempCo: 100 ppm/C; Value_Code: 470R; U/M: EA; Value: 470; SizeX_mm: 1; SizeY_mm: 0.5; SizeZ_mm: 0.6; Value2: 0.063W; AEC Qualified: N; VDC_V: 50V; AEC Category: Q200
R174 R175 = CMP-0026825-5: RES, 10 k, 5%, 0.063 W, AEC-Q200 Grade 0, 0402; Manufacturer: Vishay-Dale; Value: 10k; Value_Code: 10k0; Power_W: 63mW; Value2: 0.063W; VDC_V: 50V; TempCo: 200 ppm/C; SizeArea_mm2: 0.5; SizeX_mm: 1; SizeZ_mm: 0.6; EIA_Code: E24; AEC Category: Q200; AEC Qualified: Y; AEC Grade: 0
R176 = CMP-0026413-2: RES, 4.87 k, 1%, 0.063 W, AEC-Q200 Grade 0, 0402; Manufacturer: Vishay-Dale; Value: 4.87k; Value_Code: 4k87; Power_W: 63mW; Value2: 0.063W; VDC_V: 50V; TempCo: 100 ppm/C; SizeArea_mm2: 0.5; SizeX_mm: 1; SizeZ_mm: 0.6; EIA_Code: E96; AEC Category: Q200; AEC Qualified: Y; AEC Grade: 0
R177 = CMP-0026946-3: RES, 51, 5%, 0.063 W, AEC-Q200 Grade 0, 0402; Manufacturer: Vishay-Dale; Value: 51; Value_Code: 51R0; Power_W: 63mW; Value2: 0.063W; VDC_V: 50V; TempCo: 200 ppm/C; SizeArea_mm2: 0.5; SizeX_mm: 1; SizeZ_mm: 0.6; EIA_Code: E24; AEC Category: Q200; AEC Qualified: Y; AEC Grade: 0
U2 = CMP-0077953-1: MSP432E401YTPDT, PDT0128A (TQFP-128); Alternate PartNumber: MSP432E401YTPDTR; Alternate Manufacturer: Texas Instruments; SizeAreaWB_mm2: 324; SizeZ_mm: 1.2; SizeX_mm: 16; SizeArea_mm2: 256; CompType: IC; AEC Qualified: N; AEC Category: Q200
U4 U5 = CMP-0043115-3: 4-Channel ESD Protection Array for High-Speed Data Interfaces, DRY0006A (USON-6); Manufacturer: Texas Instruments; IO Leakage Current(nA): 1; USB High Speed: TRUE; IO Capacitance(Typ)(pF): 1.6; Eco-Plan: Green (RoHS & no Sb/Br); IEC 61000-4-2 Contact(+/- kV): 8; Breakdown Voltage(Min)(V): 6; IEC 61000-4-2 Air-Gap(+/- kV): 12; AEC Category: Q200; AEC Qualified: N; CompType: IC; SizeAreaWB_mm2: 4.9; SizeArea_mm2: 1.45; SizeX_mm: 1.0; SizeZ_mm: 0.6; Rating: Catalog
U26 = CMP-0076064-3: High-Speed, Low-Power, Robust EMC Quad-Channel Digital Isolator, DW0016B (SOIC-16); Manufacturer: Texas Instruments; Green_Lifecycle: Active; AEC Category: Q200; CompType: IC; Green_REACh: Passed; SizeAreaWB_mm2: 152.52; SizeX_mm: 10.4; Rating: Catalog; SizeY_mm: 10.3; AEC Qualified: N; SizeZ_mm: 2.65; SizeArea_mm2: 107.12
U27 = CMP-0078446-2: High Speed, Robust EMC Triple-Channel Digital Isolators, DW0016B (SOIC-16); Manufacturer: Texas Instruments; AEC Qualified: N; CompType: IC; Rating: Catalog; SizeArea_mm2: 107.12; SizeX_mm: 10.4; SizeAreaWB_mm2: 152.52; AEC Category: Q200; SizeZ_mm: 2.65; SizeY_mm: 10.3
Y1 = CMP-0004635-3: Crystal, 16 MHz, 8pF, SMD; Manufacturer: NDK; TaMin_C: -10°C; TaMax_C: 70°C; Frequency Stability: +/-30ppm; Frequency_Fixed: 16MHz

## Sheet MCU119A_AltRouting_Misc.SchDoc
size 431 x 279 mm; Date: Not shown in title block; ApprovedBy: Not shown in title block; CheckedBy: Not shown in title block; Author: Not shown in title block; CompanyName: Not shown in title block; Engineer: Not shown in title block; Organization: Not shown in title block; Address1: Not shown in title block; Address2: Not shown in title block; Address3: Not shown in title block; Address4: Not shown in title block; DocumentNumber: 3; Revision: Use project parameter SCH_Rev; SheetNumber: 7; SheetTotal: 8; PageSetup: Record=PageOptions¦CenterHorizontal=True¦CenterVertical=True¦PrintScale=1.00¦XCorrection=1.00¦YCorrection=1.00¦PrintKind=0¦BorderSize=5000000¦LeftOffset=0¦BottomOffset=0¦Orientation=2¦PaperLength=1000¦PaperWidth=1000¦Scale=100¦PaperSource=15¦PrintQuality=600¦MediaType=1¦DitherType=10¦PaperKind=Letter¦PrintScaleMode=1
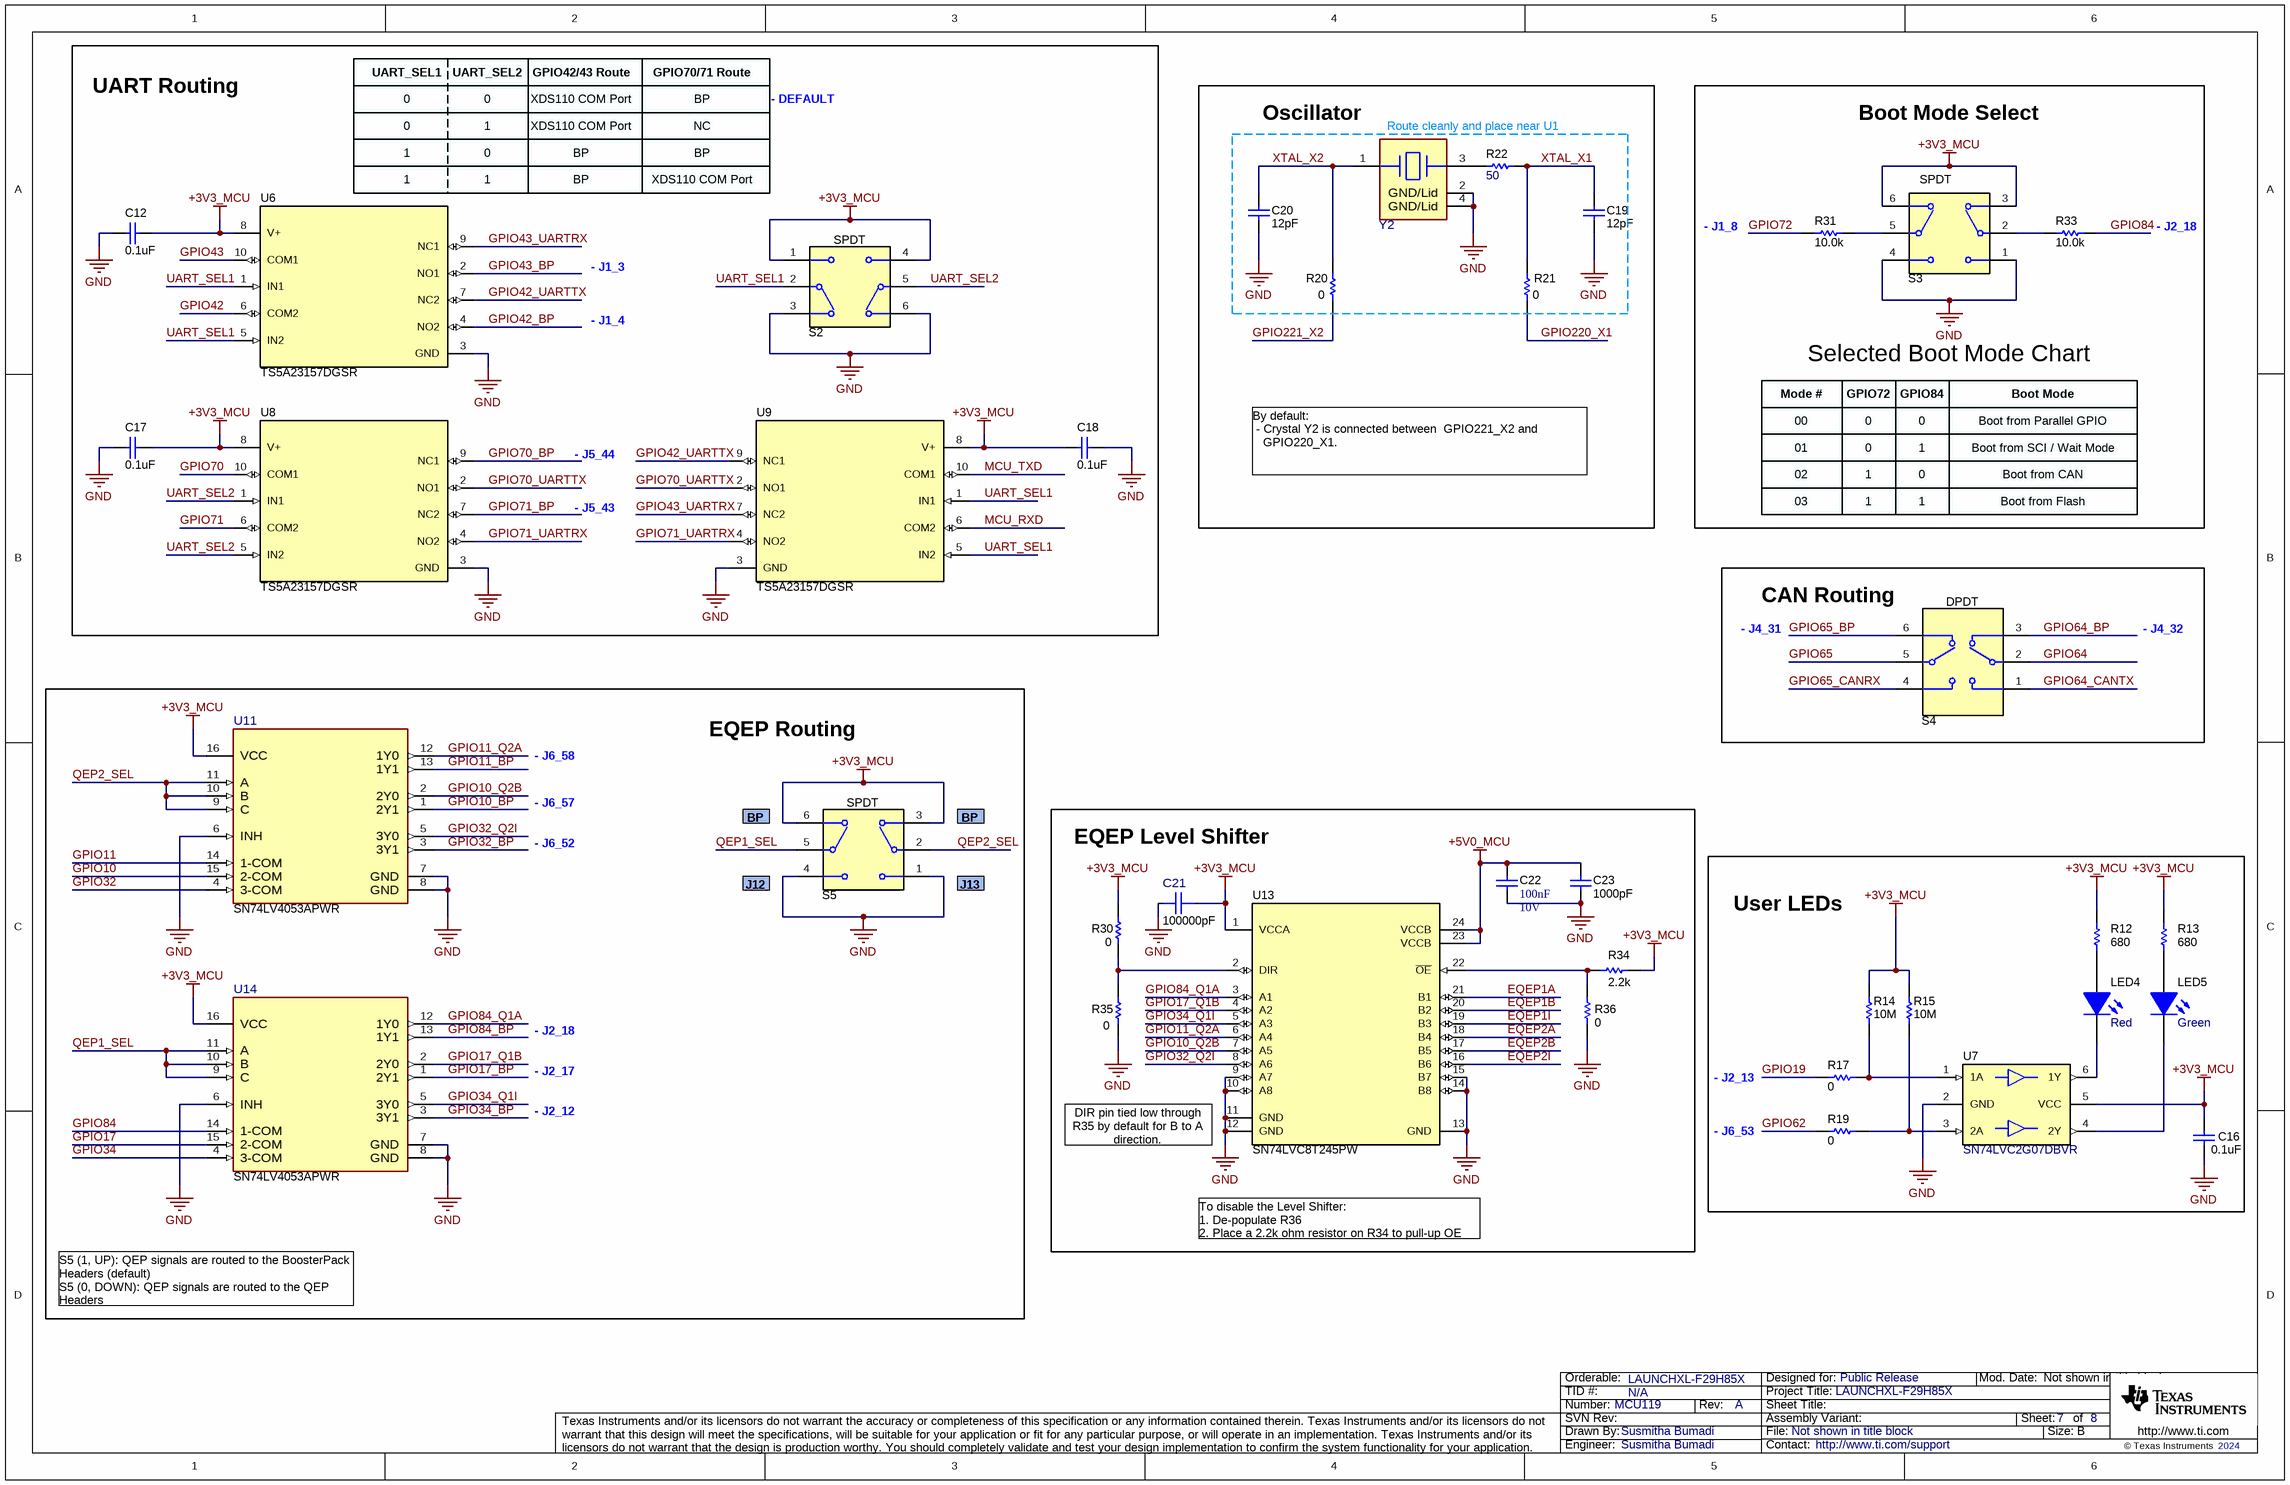
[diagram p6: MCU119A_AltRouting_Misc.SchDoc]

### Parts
C12  ValueDisplayed: 0.1uF  [0402]  (hidden comment: 885012205037)
C16  ValueDisplayed: 0.1uF  [0402]  (hidden comment: 885012205037)
C17  ValueDisplayed: 0.1uF  [0402]  (hidden comment: 885012205037)
C18  ValueDisplayed: 0.1uF  [0402]  (hidden comment: 885012205037)
C19  ValueDisplayed: 12pF  [0402]  (hidden comment: C0402C120J3GACAUTO)
C20  ValueDisplayed: 12pF  [0402]  (hidden comment: C0402C120J3GACAUTO)
C21  ValueDisplayed: 100000pF  [FP-885012205018_0402-MFG]  (hidden comment: 885012205018)
C22  Cap_F: 100nF  VDC_V: 10V  [0603]  (hidden comment: C0603C104K8RACTU)
C23  ValueDisplayed: 1000pF  [0402]  (hidden comment: 885012205061)
LED4  value Red  [WL-SMCW_RED_0805]  (hidden comment: 150080SS75000)
LED5  value Green  [LED_LTST-C171]  (hidden comment: LTST-C171GKT)
R12  ValueDisplayed: 680  [0402]  (hidden comment: CRCW0402680RJNED)
R13  ValueDisplayed: 680  [0402]  (hidden comment: CRCW0402680RJNED)
R14  ValueDisplayed: 10M  [0402]  (hidden comment: CRCW040210M0JNED)
R15  ValueDisplayed: 10M  [0402]  (hidden comment: CRCW040210M0JNED)
R17  ValueDisplayed: 0  [0603]  (hidden comment: CRCW06030000Z0EA)
R19  ValueDisplayed: 0  [0603]  (hidden comment: CRCW06030000Z0EA)
R20  ValueDisplayed: 0  [0603]  (hidden comment: CRCW06030000Z0EA)
R21  ValueDisplayed: 0  [0603]  (hidden comment: CRCW06030000Z0EA)
R22  ValueDisplayed: 50  [0603]  (hidden comment: FC0603E50R0BTBST1)
R30  ValueDisplayed: 0  [0603]  (hidden comment: CRCW06030000Z0EA)
R31  ValueDisplayed: 10.0k  [0603]  (hidden comment: RC0603FR-0710KL)
R33  ValueDisplayed: 10.0k  [0603]  (hidden comment: RC0603FR-0710KL)
R34  ValueDisplayed: 2.2k  [0603]  (hidden comment: CRCW06032K20JNEA)
R35  ValueDisplayed: 0  [0603]  (hidden comment: CRCW06030000Z0EA)
R36  ValueDisplayed: 0  [0603]  (hidden comment: CRCW06030000Z0EA)
S2  CAS-D20TA  [SW_CAS-D20TA]  (value not drawn)
S3  CAS-D20TA  [SW_CAS-D20TA]  (value not drawn)
S4  CAS-220TA  [SW_CAS-220TA]  (value not drawn)
S5  CAS-D20TA  [SW_CAS-D20TA]  (value not drawn)
U6  TS5A23157DGSR  [DGS0010A_N]
U7  SN74LVC2G07DBVR  [DBV0006A_N]
U8  TS5A23157DGSR  [DGS0010A_N]
U9  TS5A23157DGSR  [DGS0010A_N]
U11  SN74LV4053APWR  [PW0016A-MFG]
U13  SN74LVC8T245PW  [PW0024A_N]
U14  SN74LV4053APWR  [PW0016A-MFG]
Y2  830108207209  [FP-830108207209_SMT_CRYSTAL_3MM2_2MM5-MFG]  (value not drawn)

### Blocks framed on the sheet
UART Routing: C12 C17 C18 S2 U6 U8 U9
Oscillator: C19 C20 R20-R22 Y2
Selected Boot Mode Chart: R31 R33 S3
CAN Routing: S4
EQEP Routing: S5 U11 U14
EQEP Level Shifter: C21-C23 R30 R34-R36 U13
User LEDs: C16 LED4 LED5 R12-R15 R17 R19 U7

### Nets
+3V3_MCU: C12.2 C16.1 C17.2 C18.1 C21.1 R12.2 R13.2 R14.2 R15.2 R30.2 R34.2 S2.1 S2.4 S3.3 S3.6 S5.3 S5.6 U6.8(V+) U7.5(VCC) U8.8(V+) U9.8(V+) U11.16(VCC) U13.1(VCCA) U14.16(VCC)
+5V0_MCU: C22.1 C23.1 U13.23(VCCB) U13.24(VCCB)
GND: C12.1 C16.2 C17.1 C18.2 C19.2 C20.2 C21.2 C22.2 C23.2 R35.1 R36.2 S2.3 S2.6 S3.1 S3.4 S5.1 S5.4 U6.3(GND) U7.2(GND) U8.3(GND) U9.3(GND) U11.6(INH) U11.7(GND) U11.8(GND) U13.9(A7) U13.10(A8) U13.11(GND) U13.12(GND) U13.13(GND) U13.14(B8) U13.15(B7) U14.6(INH) U14.7(GND) U14.8(GND) Y2.2(GND/Lid) Y2.4(GND/Lid)
EQEP1A: U13.21(B1)
EQEP1B: U13.20(B2)
EQEP1I: U13.19(B3)
EQEP2A: U13.18(B4)
EQEP2B: U13.17(B5)
EQEP2I: U13.16(B6)
GPIO10: U11.15(2-COM)
GPIO10_BP: U11.1(2Y1)
GPIO10_Q2B: U11.2(2Y0) U13.7(A5)
GPIO11: U11.14(1-COM)
GPIO11_BP: U11.13(1Y1)
GPIO11_Q2A: U11.12(1Y0) U13.6(A4)
GPIO17: U14.15(2-COM)
GPIO17_BP: U14.1(2Y1)
GPIO17_Q1B: U13.4(A2) U14.2(2Y0)
GPIO19: R17.1
GPIO32: U11.4(3-COM)
GPIO32_BP: U11.3(3Y1)
GPIO32_Q2I: U11.5(3Y0) U13.8(A6)
GPIO34: U14.4(3-COM)
GPIO34_BP: U14.3(3Y1)
GPIO34_Q1I: U13.5(A3) U14.5(3Y0)
GPIO42: U6.6(COM2)
GPIO42_BP: U6.4(NO2)
GPIO42_UARTTX: U6.7(NC2) U9.9(NC1)
GPIO43: U6.10(COM1)
GPIO43_BP: U6.2(NO1)
GPIO43_UARTRX: U6.9(NC1) U9.7(NC2)
GPIO62: R19.1
GPIO64: S4.2
GPIO64_BP: S4.3
GPIO64_CANTX: S4.1
GPIO65: S4.5
GPIO65_BP: S4.6
GPIO65_CANRX: S4.4
GPIO70: U8.10(COM1)
GPIO70_BP: U8.9(NC1)
GPIO70_UARTTX: U8.2(NO1) U9.2(NO1)
GPIO71: U8.6(COM2)
GPIO71_BP: U8.7(NC2)
GPIO71_UARTRX: U8.4(NO2) U9.4(NO2)
GPIO72: R31.1
GPIO84: R33.2 U14.14(1-COM)
GPIO84_BP: U14.13(1Y1)
GPIO84_Q1A: U13.3(A1) U14.12(1Y0)
GPIO220_X1: R21.1
GPIO221_X2: R20.1
MCU_RXD: U9.6(COM2)
MCU_TXD: U9.10(COM1)
QEP1_SEL: S5.5(C) U14.9(C) U14.10(B) U14.11(A)
QEP2_SEL: S5.2(C) U11.9(C) U11.10(B) U11.11(A)
UART_SEL1: S2.2(C) U6.1(IN1) U6.5(IN2) U9.1(IN1) U9.5(IN2)
UART_SEL2: S2.5(C) U8.1(IN1) U8.5(IN2)
XTAL_X1: C19.1 R21.2 R22.2
XTAL_X2: C20.1 R20.2 Y2.1(1_Crystal)
NetLED4_1: LED4.1(K) U7.6(1Y)
NetLED4_2: LED4.2(A) R12.1
NetLED5_1: LED5.1(A) R13.1
NetLED5_2: LED5.2(K) U7.4(2Y)
NetR14_1: R14.1 R17.2 U7.1(1A)
NetR15_1: R15.1 R19.2 U7.3(2A)
NetR22_1: R22.1 Y2.3(2_Crystal)
NetR30_1: R30.1 R35.2 U13.2(DIR)
NetR31_2: R31.2 S3.5(C)
NetR33_1: R33.1 S3.2(C)
NetR34_1: R34.1 R36.1 U13.22(~{OE})

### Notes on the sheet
- UART_SEL1
- 0
- UART_SEL2
- GPIO42/43 Route
- XDS110 COM Port
- GPIO70/71 Route
- BP
- - DEFAULT
- 1
- NC
- Route cleanly and place near U1
- Boot Mode Select
- (near U6) 1
- - J1_8
- (near S3) SPDT
- - J2_18
- - J1_3
- (near S2) SPDT
- - J1_4
- Mode #
- 00
- GPIO72
- GPIO84
- Boot Mode
- Boot from Parallel GPIO
- - J5_44
- By default:
  - Crystal Y2 is connected between  GPIO221_X2 and
  GPIO220_X1.
- 01
- 02
- 03
- Boot from SCI / Wait Mode
- Boot from CAN
- Boot from Flash
- - J5_43
- - J4_31
- (near S4) DPDT
- - J4_32
- - J6_58
- - J6_57
- - J6_52
- (near S5) SPDT
- J12
- J13
- - J2_17
- - J2_12
- - J2_13
- (near U13) DIR pin tied low through R35 by default for B to A direction.
- - J6_53
- To disable the Level Shifter:
  1. De-populate R36
  2. Place a 2.2k ohm resistor on R34 to pull-up OE
- S5 (1, UP): QEP signals are routed to the BoosterPack Headers (default)
  S5 (0, DOWN): QEP signals are routed to the QEP Headers

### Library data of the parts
C12 C16-C18 = CMP-0006228-2: as C128 on sheet MCU119A_USB_and_Power
C19 C20 = CMP-0006239-2: CAP, CERM, 12 pF, 25 V, +/- 5%, C0G/NP0, AEC-Q200 Grade 1, 0402; Manufacturer: Kemet; TaMin_C: -55°C; Polarized: N; SizeAreaWB_mm2: 3; Value1: Unknown; U/M: EA; Value: 12pF; TaMax_C: 125°C; SizeZ_mm: 0.6; SizeX_mm: 1; SizeY_mm: 0.5; Value2: 25V; AEC Qualified: Y; AEC Category: Q200
C21 = CMP-0090362-1: as C137 on sheet MCU119A_XDS110_MCU
C22 = CMP-0006862-5: as C75 on sheet MCU119A_USB_and_Power
C23 = CMP-0006231-2: CAP, CERM, 1000 pF, 50 V, +/- 10%, X7R, 0402; Manufacturer: Wurth Elektronik; Polarized: N; Value: 1000pF; U/M: EA; Cap_F: 1nF; Value1: Unknown; VDC_V: 50V; TaMin_C: -55°C; TaMax_C: 125°C; SizeArea_mm2: 0.5; SizeAreaWB_mm2: 3; SizeX_mm: 1; SizeZ_mm: 0.6; AEC Category: Q200
LED4 = CMP-0002951-3: as LED1 on sheet MCU119A_USB_and_Power
LED5 = CMP-0002830-3: LED, Green, SMD; Manufacturer: Lite-On; Type: AlInGaP; Vf_V: 2.1V; Io_A: 20A; Value1: W; SizeAreaWB_mm2: 6.75; SizeArea_mm2: 2.5; SizeX_mm: 2; SizeY_mm: 1.25; SizeZ_mm: 1.2
R12 R13 = CMP-0026962-3: RES, 680, 5%, 0.063 W, AEC-Q200 Grade 0, 0402; Manufacturer: Vishay-Dale; Power_W: 63mW; TempCo: 200 ppm/C; Value_Code: 680R; Value: 680; EIA_Code: E24; SizeX_mm: 1; SizeY_mm: 0.5; SizeZ_mm: 0.6; Value2: 0.063W; AEC Qualified: Y; VDC_V: 50V; AEC Category: Q200; AEC Grade: 0
R14 R15 = CMP-0026826-2: RES, 10 M, 5%, 0.063 W, AEC-Q200 Grade 0, 0402; Manufacturer: Vishay-Dale; Value: 10Meg; Value_Code: 10M0; Power_W: 63mW; Value2: 0.063W; VDC_V: 50V; TempCo: 200 ppm/C; SizeArea_mm2: 0.5; SizeX_mm: 1; SizeZ_mm: 0.6; EIA_Code: E24; AEC Category: Q200; AEC Qualified: Y; AEC Grade: 0
R17 R19-R21 R30 R35 R36 = CMP-0025697-4: RES, 0, 5%, 0.1 W, AEC-Q200 Grade 0, 0603; Manufacturer: Vishay-Dale; Value: 0; Value_Code: 0000; Power_W: 100mW; Value2: 0.1W; VDC_V: 75V; TempCo: 200 ppm/C; SizeArea_mm2: 1.28; SizeX_mm: 1.6; SizeY_mm: 0.8; SizeZ_mm: 1; EIA_Code: E24; AEC Category: Q200; AEC Qualified: Y
R22 = CMP-0023387-3: RES, 50, 0.1%, 0.125 W, 0603; Manufacturer: Vishay Thin Film; Power_W: 125mW; TempCo: 25 ppm/C; Value_Code: 50R0; U/M: EA; Value: 50; SizeX_mm: 1.6; SizeY_mm: 0.8; SizeZ_mm: 1; Value2: 0.125W; SizeArea_mm2: 1.28; AEC Qualified: N; VDC_V: 50V; AEC Category: Q200
R31 R33 = CMP-0022746-5: RES, 10.0 k, 1%, 0.1 W, 0603; Manufacturer: Yageo; Power_W: 100mW; TempCo: 100 ppm/C; Value_Code: 10k0; Value: 10.0k; EIA_Code: E96; Res_ohm: 10k; SizeX_mm: 1.6; SizeY_mm: 0.8; SizeZ_mm: 1; Value2: 0.1W; SizeArea_mm2: 1.28; AEC Qualified: N; VDC_V: 75V; AEC Category: Q200; SizeAreaWB_mm2: 4.68
R34 = CMP-0025769-4: RES, 2.2 k, 5%, 0.1 W, AEC-Q200 Grade 0, 0603; Manufacturer: Vishay-Dale; Value: 2.2k; Value_Code: 2k20; Power_W: 100mW; Value2: 0.1W; VDC_V: 75V; TempCo: 200 ppm/C; SizeArea_mm2: 1.28; SizeX_mm: 1.6; SizeY_mm: 0.8; SizeZ_mm: 1; EIA_Code: E24; AEC Category: Q200; AEC Qualified: Y; AEC Grade: 0
S2 S5 = CMP-0002233-1: Switch, Dual SPDT,  2 Pos, 0.1A, 6VDC, SMD; Manufacturer: Copal Electronics; VDC_V: 6V; SwitchFunction: On-On; PositionCount: 2; CurrentRating_mA: 100A
S3 = CMP-0002233-1: Switch, Dual SPDT,  2 Pos, 0.1A, 6VDC, SMD; Manufacturer: Copal Electronics; CurrentRating_mA: 100A; SwitchFunction: On-On; VDC_V: 6V; PositionCount: 2
S4 = CMP-0002123-2: SLIDE SWITCH DPDT  .1A, SMT; Manufacturer: Copal Electronics; VDC_V: 6V; SwitchFunction: On-On; PositionCount: 2; CurrentRating_mA: 100A
U6 U8 U9 = CMP-0067418-1: DUAL 10-Ohm SPDT ANALOG SWITCH, DGS0010A (VSSOP-10); Alternate PartNumber: TS5A23157DGST; Alternate Manufacturer: Texas Instruments; Green_Lifecycle: Active; SizeAreaWB_mm2: 23.6; Green_REACh: Passed; U/M: EA; SizeZ_mm: 1.1; SizeX_mm: 4.9; SizeY_mm: 3.0; SizeArea_mm2: 14.7; CompType: IC
U7 = CMP-0051789-2: Dual Buffer/Driver with Open-Drain Output, DBV0006A, LARGE T&R; Manufacturer: Texas Instruments; VCC(Min)(V): 1.65; VCC(Max)(V): 5.5; Output Type: CMOS; ICC @ Nom Voltage(Max)(mA): 0.01; Input Type: CMOS/TTL; Bits(#): 2; F @ Nom Voltage(Max)(Mhz): 150; Rating: Catalog; Technology Family: LVC; Voltage(Nom)(V): 1.8,2.5,3.3,5; Schmitt Trigger: No; Output Drive (IOL/IOH)(Max)(mA): 32/-32; tpd @ Nom Voltage(Max)(ns): 8.6,4.4,3.7,2.9; Logic: True; Sub-Family: Inverting Buffer/Driver; AEC Category: Q200; AEC Qualified: N; CompType: IC; Green_Lifecycle: Active; Green_REACh: Passed; SizeArea_mm2: 8.12; SizeAreaWB_mm2: 14.82; SizeX_mm: 2.8; SizeY_mm: 2.9; SizeZ_mm: 1.45
U11 U14 = CMP-0089841-1: 3 Circuit IC Switch 2:1 75Ohm 16-TSSOP; Manufacturer: Texas Instruments; TaMax_C: +85°C; Max Supply Voltage: 5.5V; PositionCount: 3; AEC Qualified: No; SizeZ_mm: 1.2mm; Standoff Height: 0.05mm; On State Resistance: 100-225Ω; Min Supply Voltage: 2V; -3Db Bandwith: 50MHz; Nominal Supply Current: 20uA; TaMin_C: -40°C
U13 = CMP-0066458-2: 8-Bit Dual-Supply Bus Transceiver with Configurable Voltage-Level Shifting and Three-State Outputs, PW0024A (TSSOP-24); Alternate Manufacturer: Texas Instruments; SizeAreaWB_mm2: 82.32; SizeZ_mm: 1.2; SizeX_mm: 6.4; SizeY_mm: 7.8; SizeArea_mm2: 49.92; CompType: IC; AEC Category: Q200; AEC Qualified: N; Rating: Catalog
Y2 = CMP-0093781-1: 20 MHz ±10ppm Crystal 8pF 50 Ohms 4-SMD, No Lead; Manufacturer: Wurth Electronics; SizeZ_mm: 0.8mm; Frequency Stability: 20ppm; Esr: 50; Frequency_Fixed: 20MHz

## Sheet MCU119A_Hardware.SchDoc
size 431 x 279 mm; Date: Not shown in title block; ApprovedBy: Not shown in title block; CheckedBy: Not shown in title block; Author: Not shown in title block; CompanyName: Not shown in title block; Engineer: Not shown in title block; Organization: Not shown in title block; Address1: Not shown in title block; Address2: Not shown in title block; Address3: Not shown in title block; Address4: Not shown in title block; DocumentNumber: 9; Revision: Use project parameter SCH_Rev; SheetNumber: 8; SheetTotal: 8; PageSetup: Record=PageOptions¦CenterHorizontal=True¦CenterVertical=True¦PrintScale=1.00¦XCorrection=1.00¦YCorrection=1.00¦PrintKind=0¦BorderSize=5000000¦LeftOffset=0¦BottomOffset=0¦Orientation=2¦PaperLength=1000¦PaperWidth=1000¦Scale=100¦PaperSource=15¦PrintQuality=600¦MediaType=1¦DitherType=10¦PaperKind=Letter¦PrintScaleMode=1
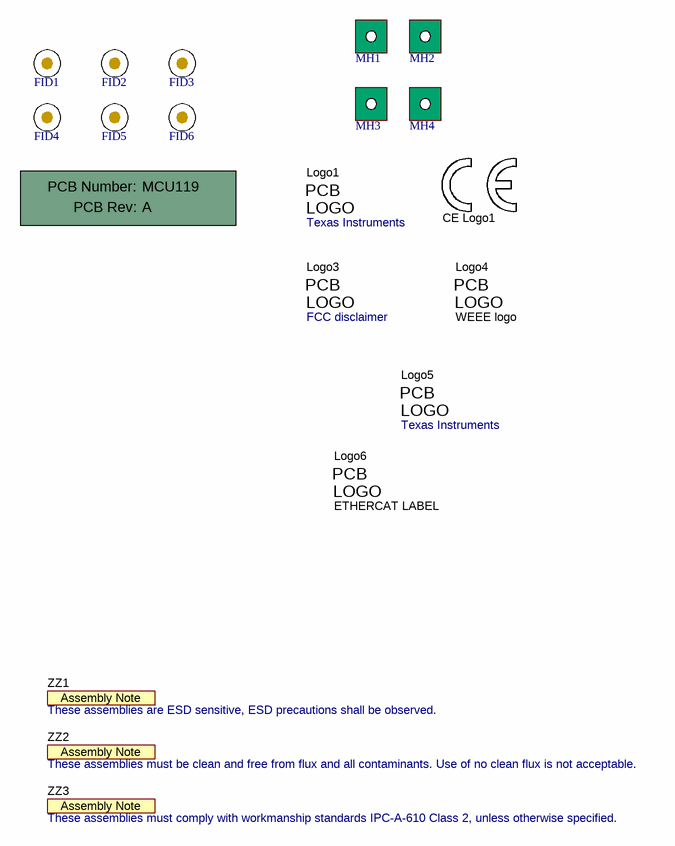
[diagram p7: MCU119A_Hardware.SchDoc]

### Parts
!PCB1  Printed Circuit Board  (value not drawn)  (mechanical)
CE_Logo1  CE Mark  [CE_Mark_5mm]  (value not drawn)  (no BOM)
FID1  Fiducial  [Fiducial10-20]  (value not drawn)
FID2  Fiducial  [Fiducial10-20]  (value not drawn)
FID3  Fiducial  [Fiducial10-20]  (value not drawn)
FID4  Fiducial  [Fiducial10-20]  (value not drawn)
FID5  Fiducial  [Fiducial10-20]  (value not drawn)
FID6  Fiducial  [Fiducial10-20]  (value not drawn)
Logo1  Texas Instruments  [TI_Stacked_Overlay_Medium]  (no BOM)
Logo3  FCC disclaimer  [FCC_disclaimer]  (no BOM)
Logo4  WEEE logo  [WEEE_Minimum]  (no BOM)
Logo5  Texas Instruments  [TI_Symbol_Overlay_Small]  (no BOM)
Logo6  ETHERCAT LABEL  [EtherCAT_label]  (no BOM)
MH1  MTG_NoPads  [NPTH125mil]  (value not drawn)  (no BOM)
MH2  MTG_NoPads  [NPTH125mil]  (value not drawn)  (no BOM)
MH3  MTG_NoPads  [NPTH125mil]  (value not drawn)  (no BOM)
MH4  MTG_NoPads  [NPTH125mil]  (value not drawn)  (no BOM)
ZZ1  These assemblies are ESD sensitive, ESD precautions shall be observed.  [AssemblyNote]  (no BOM)
ZZ2  These assemblies must be clean and free from flux and all contaminants. Use of no clean flux is not acceptable.  [AssemblyNote]  (no BOM)
ZZ3  These assemblies must comply with workmanship standards IPC-A-610 Class 2, unless otherwise specified.  [AssemblyNote]  (no BOM)

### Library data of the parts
!PCB1 = CMP-0003618-2: Manufacturer: Any; PartNumber: MCU119
CE_Logo1 = CMP-0074844-2: Manufacturer: Texas Instruments; SymbolCreator: a0412235; AEC Category: Q200; CompType: IC
FID1-FID6 = CMP-0077181-1: Fiducial mark.  There is nothing to buy or mount.
Logo1 Logo5 = CMP-0074838-1: Texas Instrument Corporate Signature; SymbolCreator: a0412235; Lib Reference: TI_Logo
Logo3 = CMP-0074847-1: FCC_disclaimer
Logo4 = CMP-0074769-4: Manufacturer: Texas Instruments; CompType: IC; AEC Category: Q200
Logo6 = CMP-0084011-3: EtherCAT logo
MH1-MH4 = CMP-0078424-2: PCB Mounting Hole, No Pad; Manufacturer: Any; Key: Mounting Hole (non-standard) No Pad
ZZ1 = CMP-0077236-1
ZZ2 = CMP-0077237-1
ZZ3 = CMP-0077238-1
